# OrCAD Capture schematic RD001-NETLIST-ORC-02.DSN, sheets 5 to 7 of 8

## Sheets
5 4: size A3
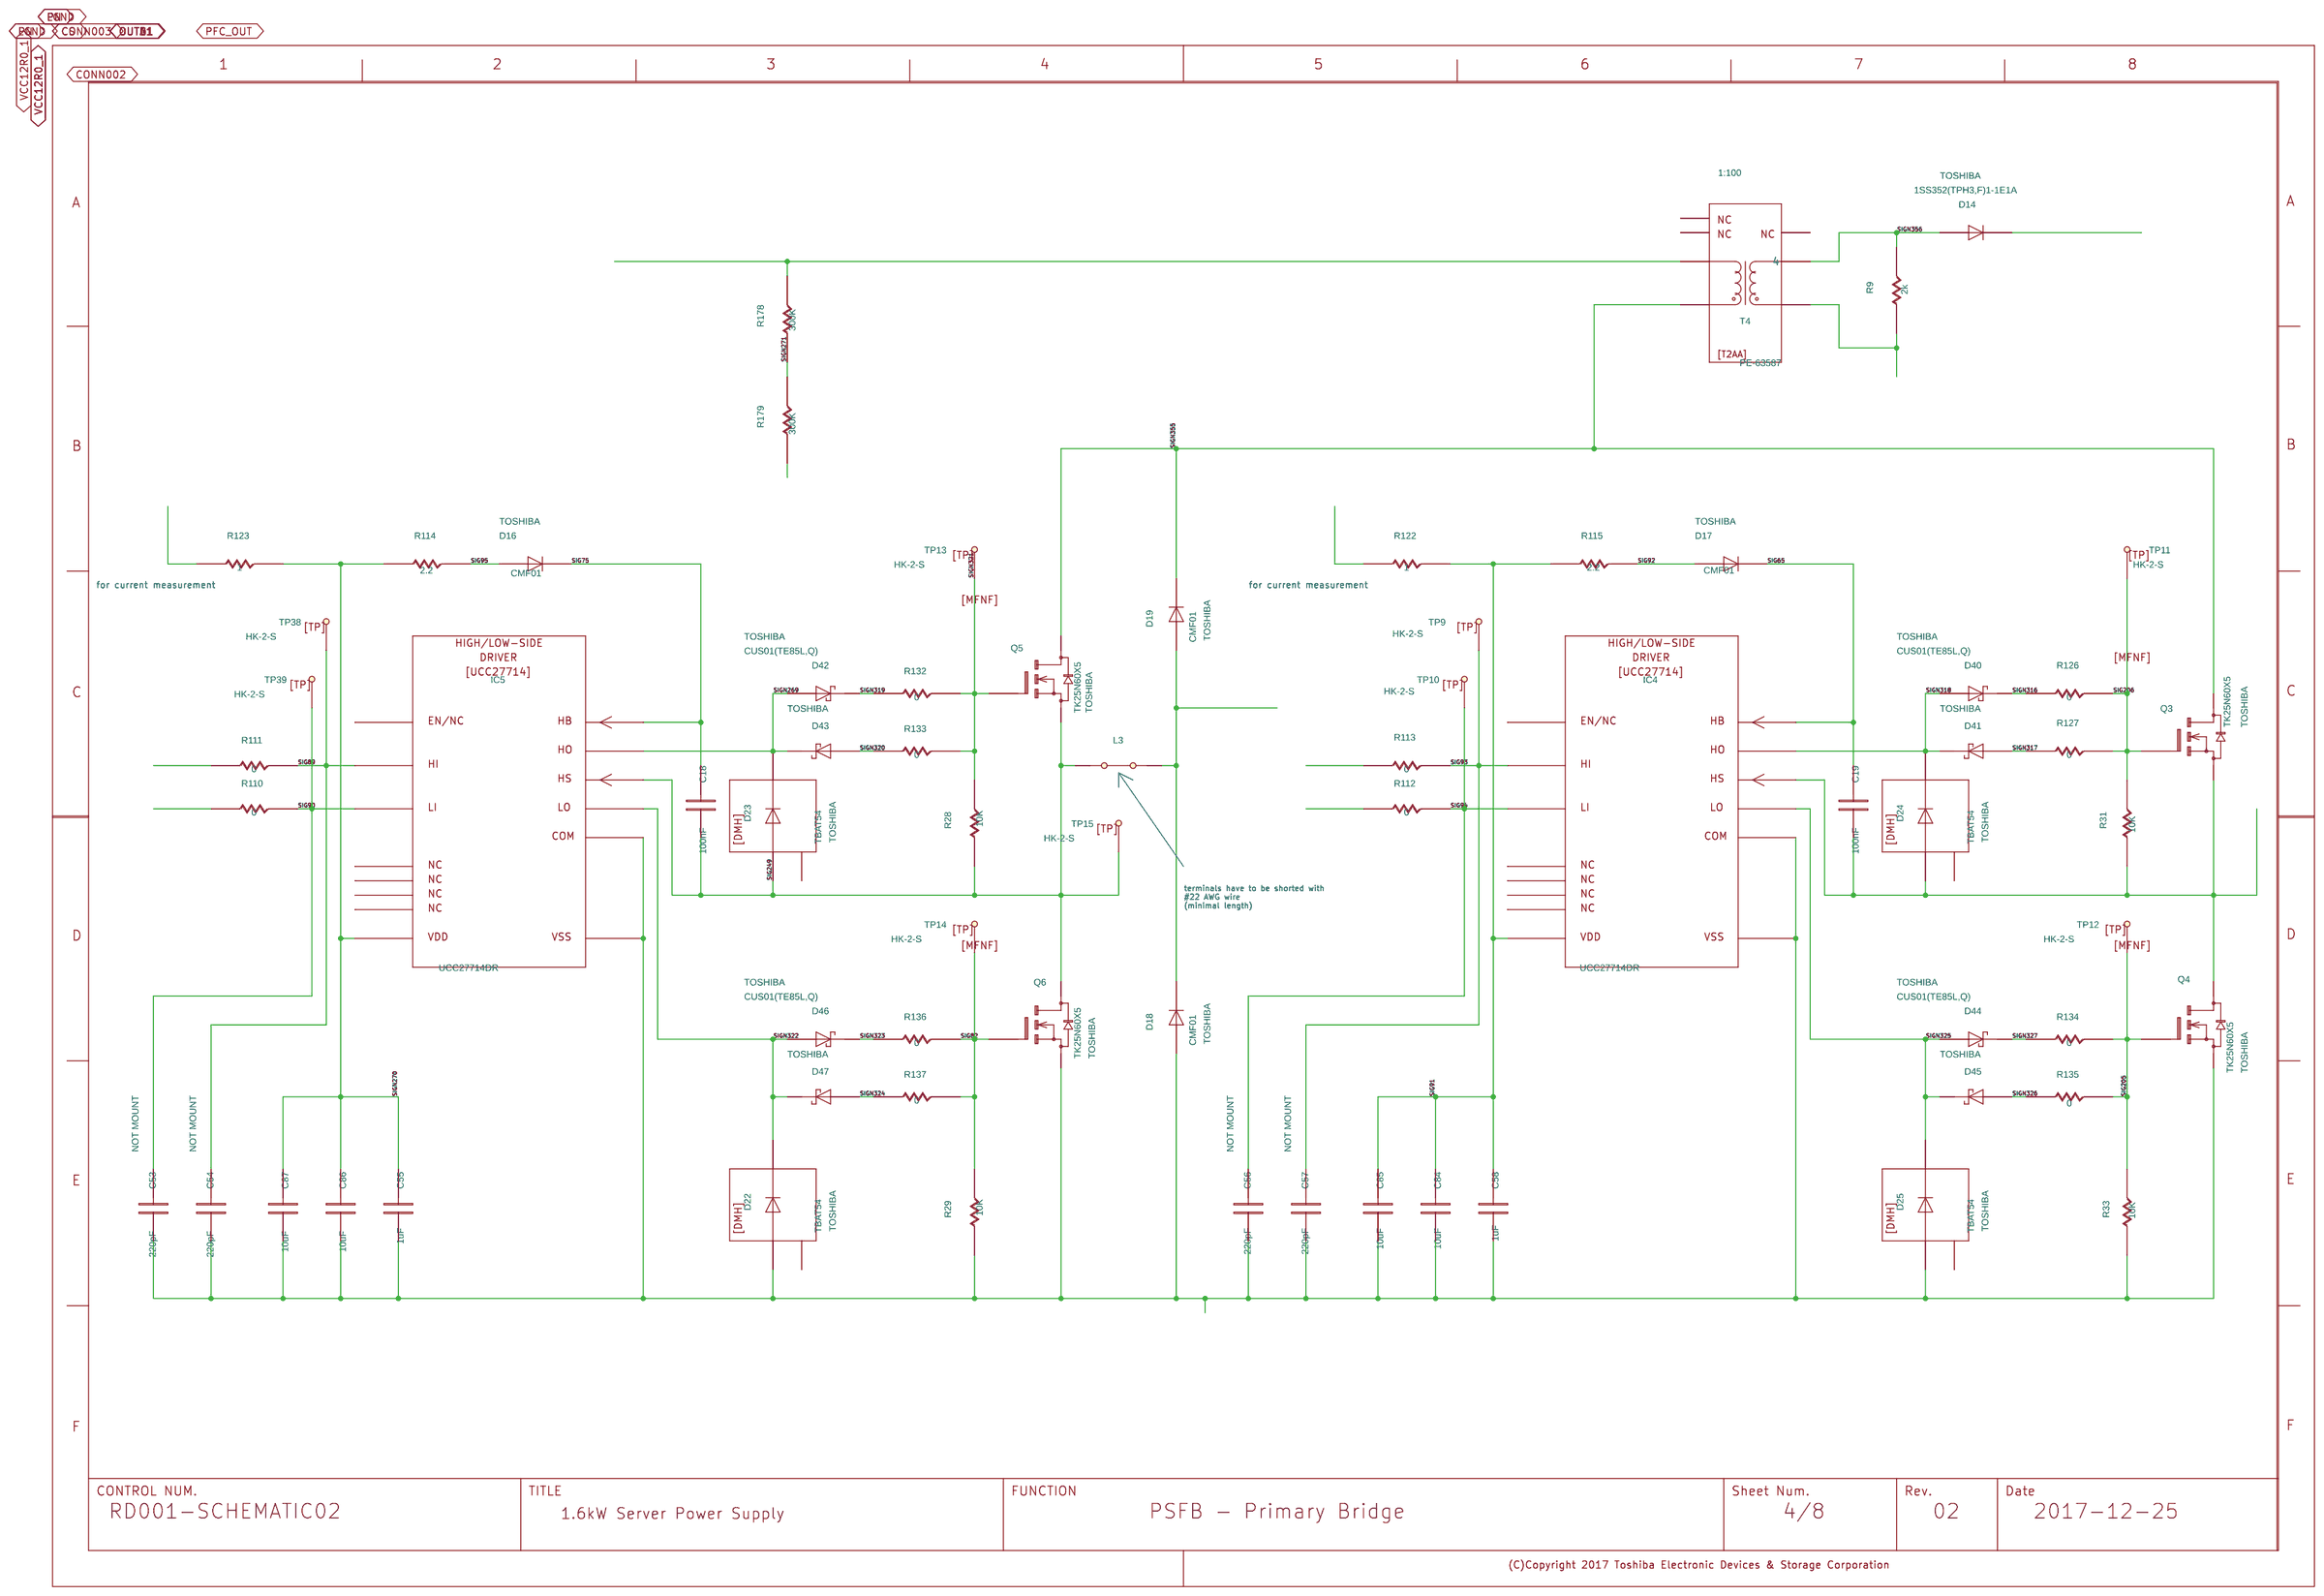
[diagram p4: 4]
6 3: size A3
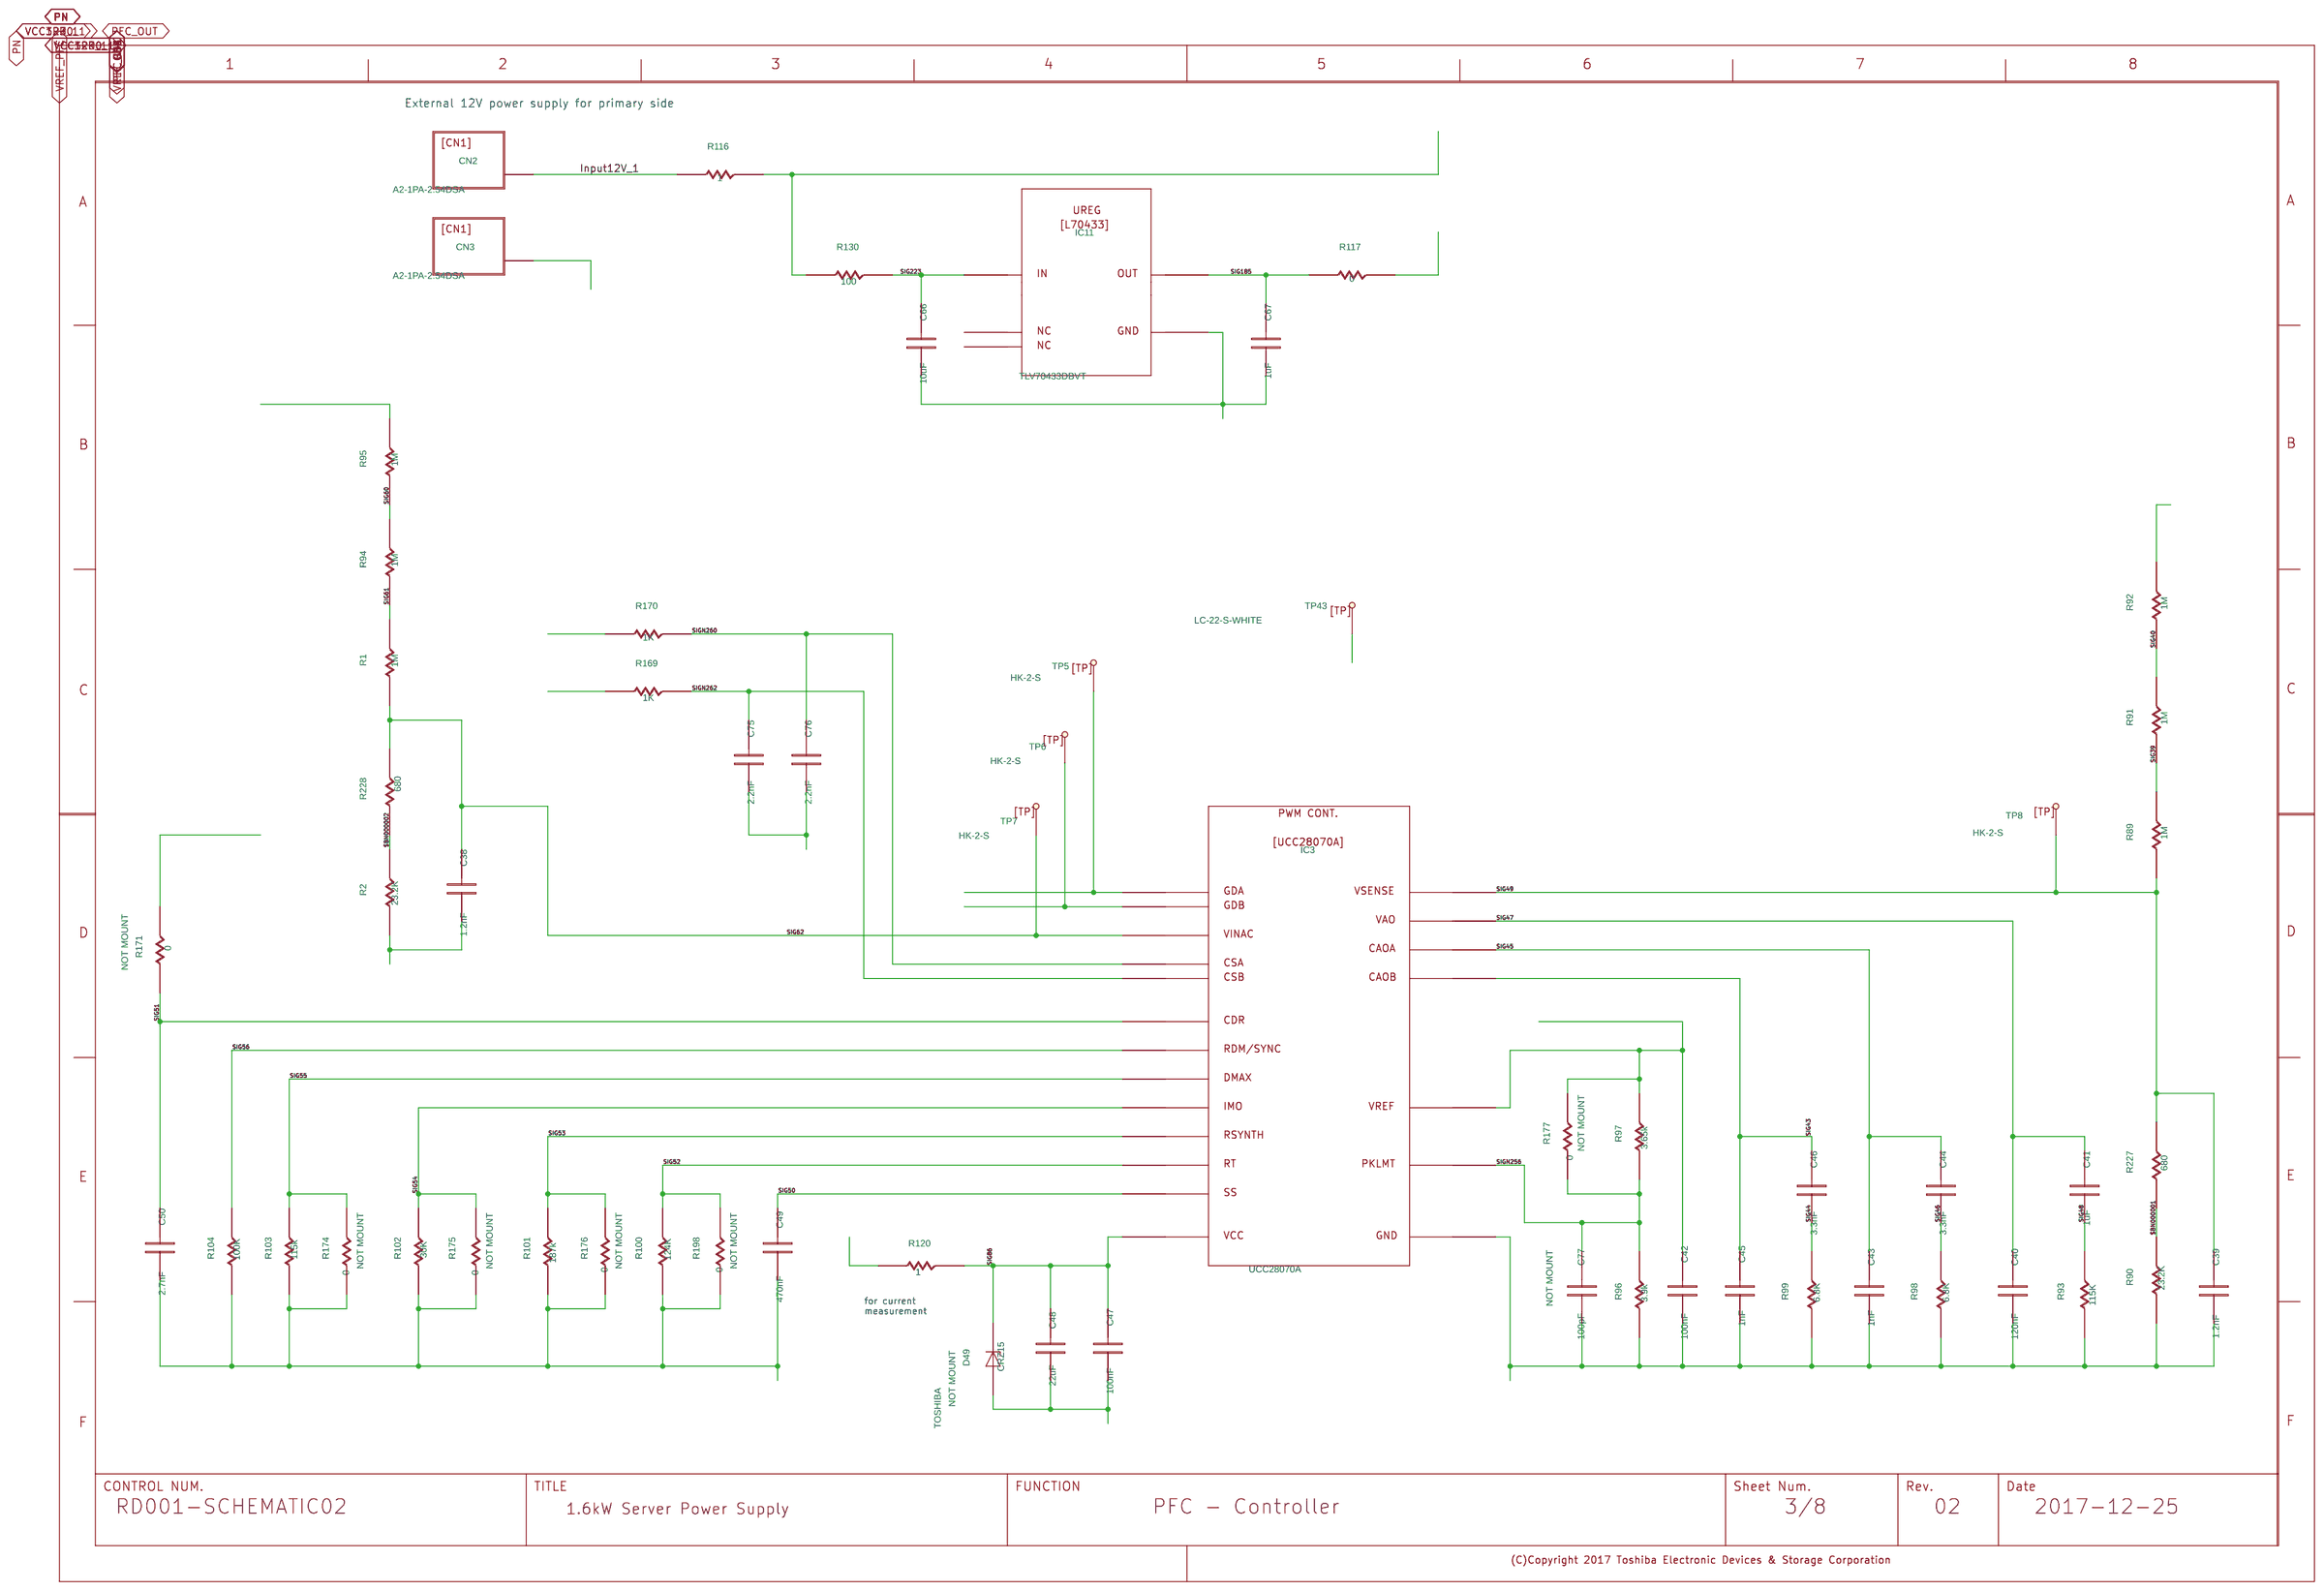
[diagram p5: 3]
7 2: size A3
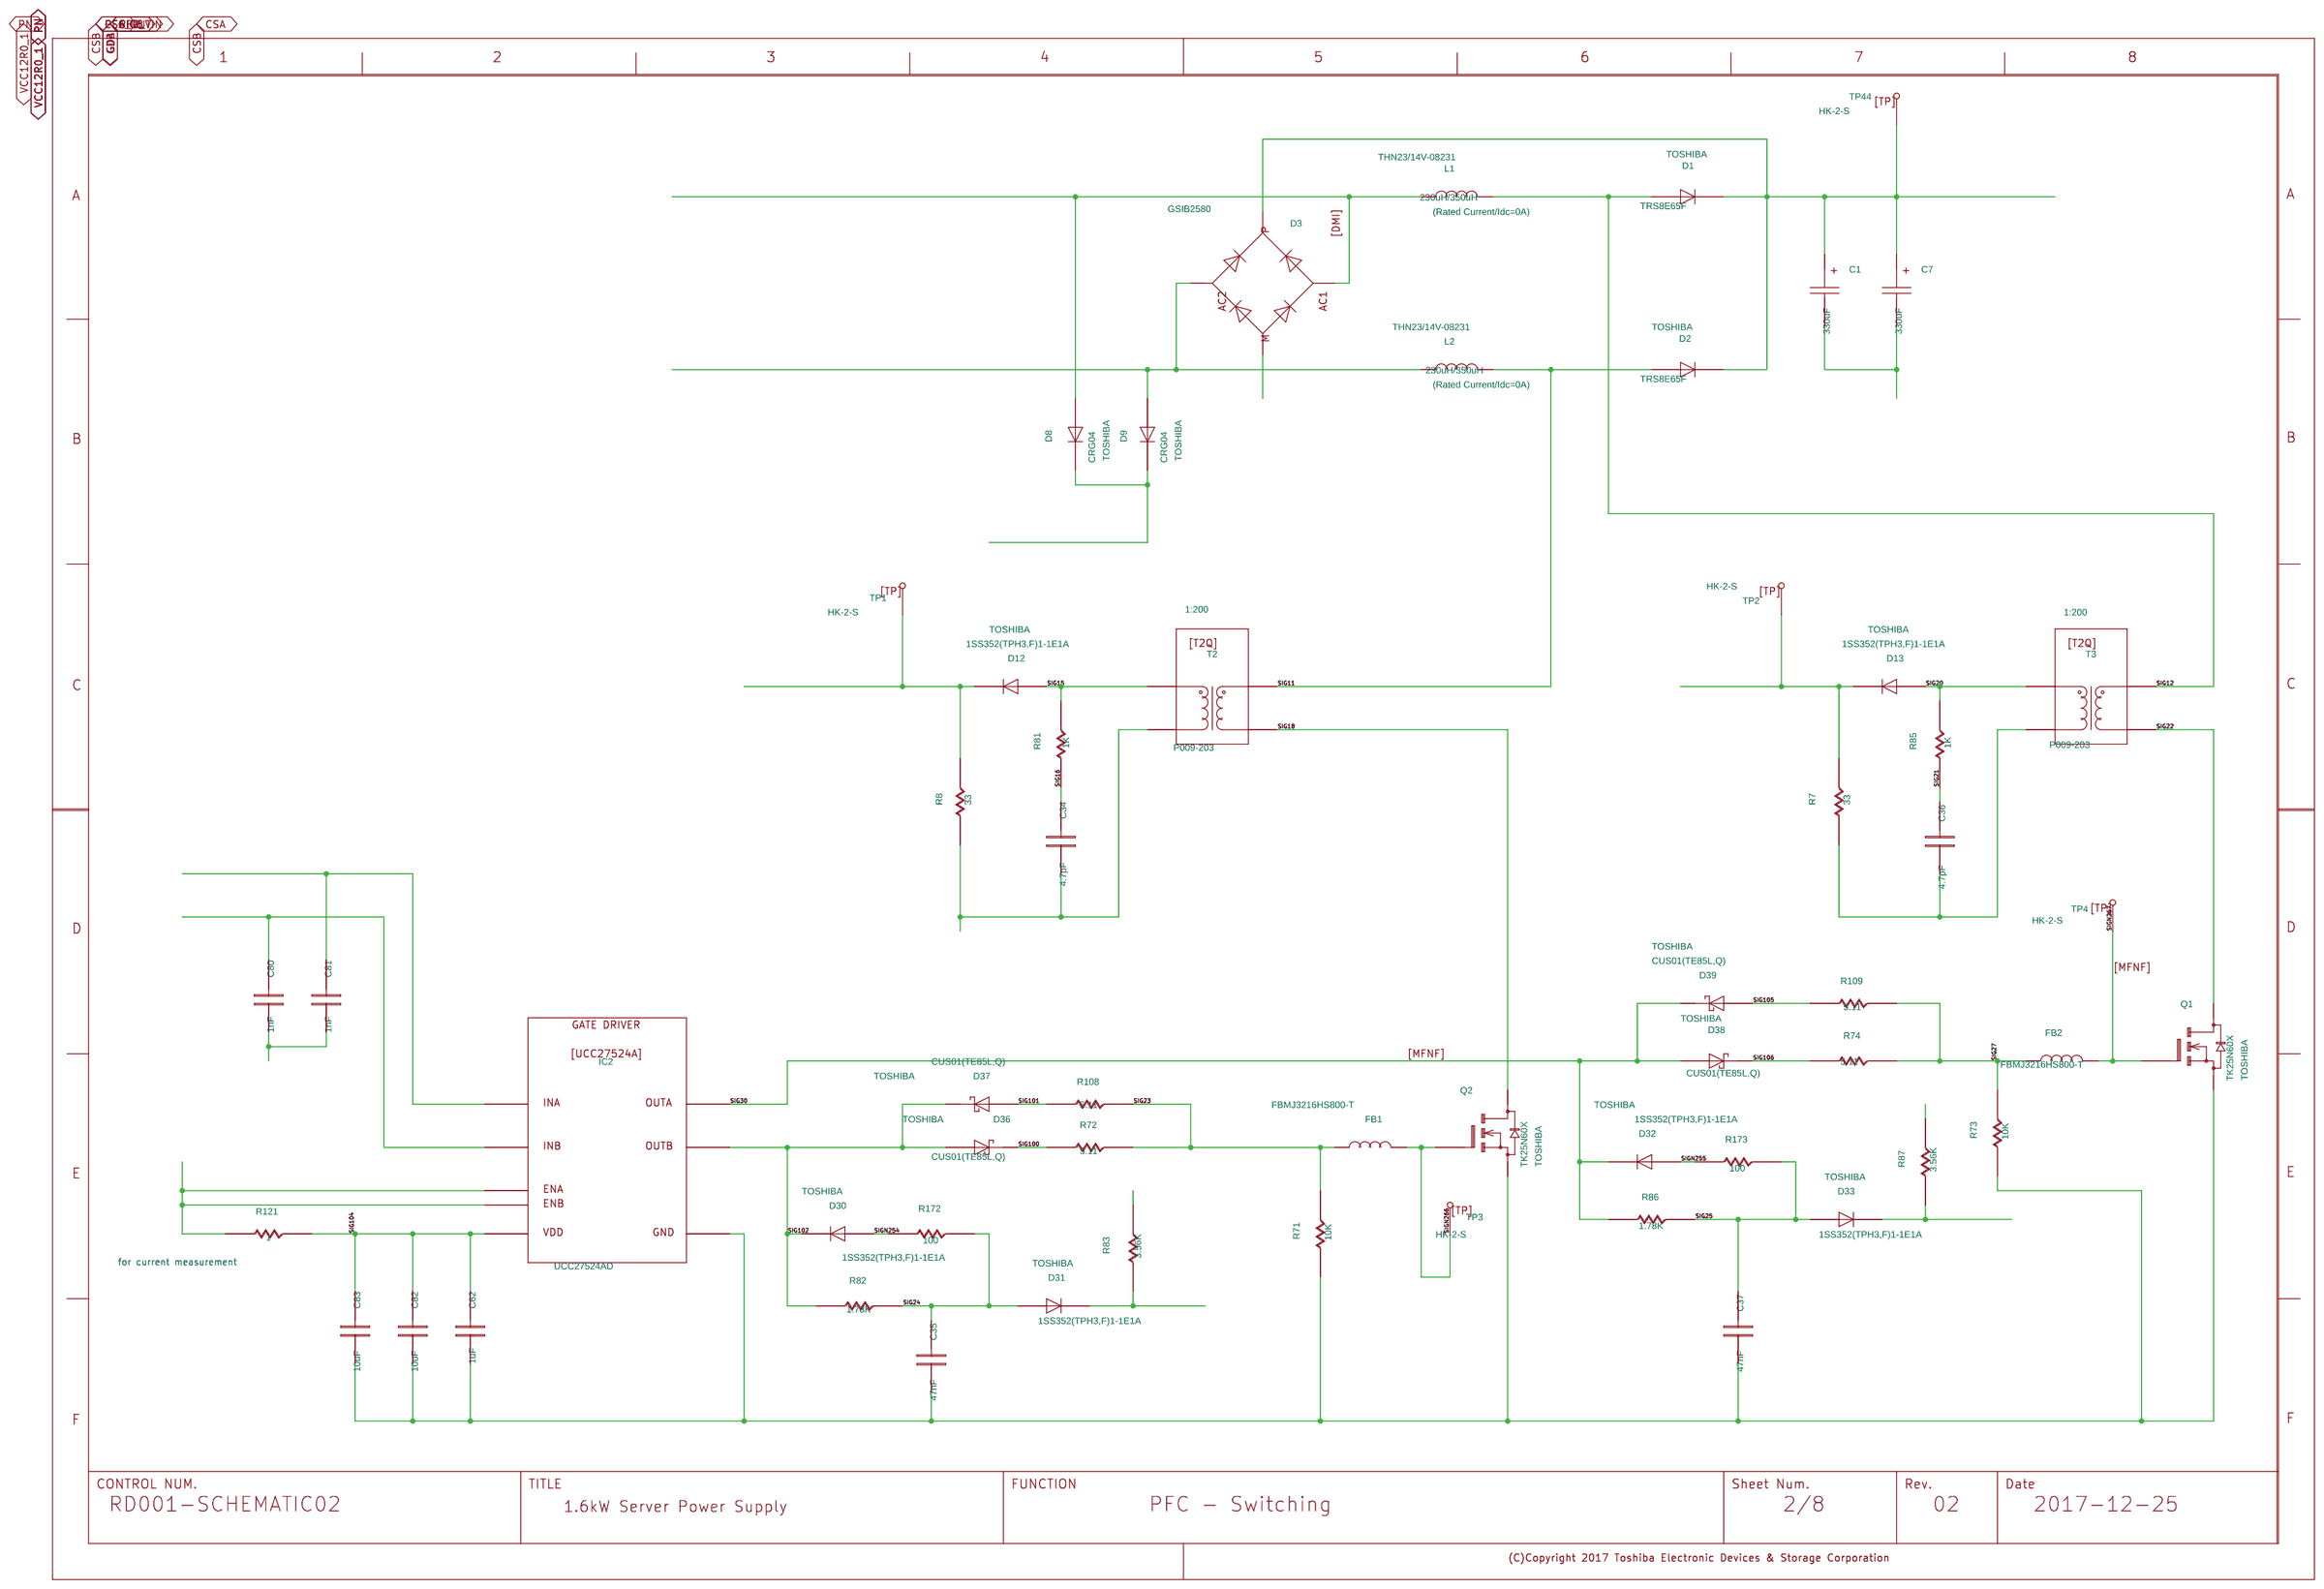
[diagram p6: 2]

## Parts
sheet 2
C1  CP
C7  CP
C34  C
C35  C
C36  C
C37  C
C62  C
C80  C
C81  C
C82  C
C83  C
D1  D
D2  D
D3  DMI
D8  D
D9  D
D12  D
D13  D
D30  D
D31  D
D32  D
D33  D
D36  SBD
D37  SBD
D38  SBD
D39  SBD
FB1  L
FB2  L
IC2  L27524
L1  L
L2  L
Q1  MFNF
Q2  MFNF
R7  R
R8  R
R71  R
R72  R
R73  R
R74  R
R81  R
R82  R
R83  R
R85  R
R86  R
R87  R
R108  R
R109  R
R121  R
R172  R
R173  R
T2  T2Q
T3  T2Q
TP1  TP
TP2  TP
TP3  TP
TP4  TP
TP44  TP
U?#6  WAKU_DEF100
sheet 3
C38  C
C39  C
C40  C
C41  C
C42  C
C43  C
C44  C
C45  C
C46  C
C47  C
C48  C
C49  C
C50  C
C66  C
C67  C
C75  C
C76  C
C77  C
CN2  CN1
CN3  CN1
D49  ZD
IC3  L28070
IC11  L70433
R1  R
R2  R
R89  R
R90  R
R91  R
R92  R
R93  R
R94  R
R95  R
R96  R
R97  R
R98  R
R99  R
R100  R
R101  R
R102  R
R103  R
R104  R
R116  R
R117  R
R120  R
R130  R
R169  R
R170  R
R171  R
R174  R
R175  R
R176  R
R177  R
R198  R
R227  R
R228  R
TP5  TP
TP6  TP
TP7  TP
TP8  TP
TP43  TP
U?#5  WAKU_DEF100
sheet 4
C18  C
C19  C
C53  C
C54  C
C55  C
C56  C
C57  C
C58  C
C84  C
C85  C
C86  C
C87  C
D14  D
D16  D
D17  D
D18  D
D19  D
D22  DMH
D23  DMH
D24  DMH
D25  DMH
D40  SBD
D41  SBD
D42  SBD
D43  SBD
D44  SBD
D45  SBD
D46  SBD
D47  SBD
IC4  L27714
IC5  L27714
L3  JP
Q3  MFNF
Q4  MFNF
Q5  MFNF
Q6  MFNF
R9  R
R28  R
R29  R
R31  R
R33  R
R110  R
R111  R
R112  R
R113  R
R114  R
R115  R
R122  R
R123  R
R126  R
R127  R
R132  R
R133  R
R134  R
R135  R
R136  R
R137  R
R178  R
R179  R
T4  T2AA
TP9  TP
TP10  TP
TP11  TP
TP12  TP
TP13  TP
TP14  TP
TP15  TP
TP38  TP
TP39  TP
U?#4  WAKU_DEF100

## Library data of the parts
C1 = CP: CAPACITANCETOLE: M; CDMASTERCADCELG: DC213N; CHIPSIZE: D35xL30; COMP: PRT_4; COMPONENTTYPE: 4; FNLEADFREETHET1GT2GMCTH1: 9_N_N; GCOUNT: 1; MAKER: RUBYCON; MAXGCOUNT: 1; NOMINALCAPACITA: 330u; OUMECLASSIFICATION: ƒAƒ‹ƒ~“d‰ðƒRƒ“ƒfƒ“ƒT; OUMEMAKER: SIT ƒ‹ƒrƒRƒ“; OUMEMAKERKATAMEI: 450MXC330M35X40; OUMEPARTTYPE: C; QUADMODEL: CON_330U; RATEDVOLTAGE: 450; SIZECODESMD: DIP; VAL1: 330uF; VAL2: 450V; VAL3: 450MXH330
C7 = CP: CAPACITANCETOLE: M; CDMASTERCADCELG: DC213N; CHIPSIZE: D35xL30; COMP: PRT_4; COMPONENTTYPE: 4; FNLEADFREETHET1GT2GMCTH1: 9_N_N; GCOUNT: 1; MAKER: RUBYCON; MAXGCOUNT: 1; NOMINALCAPACITA: 330u; OUMECLASSIFICATION: ƒAƒ‹ƒ~“d‰ðƒRƒ“ƒfƒ“ƒT; OUMEMAKER: SIT ƒ‹ƒrƒRƒ“; OUMEMAKERKATAMEI: 450MXC330M35X40; OUMEPARTTYPE: C; QUADMODEL: CON_330U; RATEDVOLTAGE: 450; SIZECODESMD: DIP; VAL1: 330uF; VAL2: 450V,}20%; VAL3: 450MXH330
C34 C36 = C: ADSMODELNAME: s_GRM1552C1H4R7CA01D; CDMASTERCADCELG: KC0005; CHIPSIZE: 1005; COMP: PRT_52; COMPONENTTYPE: 4; FNLEADFREETHET1GT2GMCTH1: N_N_N; GCOUNT: 1; MAKER: MURATA; MAXGCOUNT: 1; NOMINALCAPACITA: 4.7p; OUMECLASSIFICATION: ƒZƒ‰ƒ~ƒbƒNƒRƒ“ƒfƒ“ƒT; OUMEMAKER: MRT ºc»ì; OUMEMAKERKATAMEI: GRM1552C1H4R7CA01D; PMPRODUCTSTYPEG: DME; QUADMODEL: CON_4.7P; RATEDVOLTAGE: 50; SIZECODESMD: 1005; TEMPCHARACTERI2: CH; VAL1: 4.7pF; VAL2: 50V,}0.1pF; VAL3: GRM1555C1H4R7BA01D
C35 = C: ADSCNVFLAG: ON; ADSCOMPONENTNAME: C_1005; ADSMODELNAME: s_GCM155R11C473KA01J; CAPACITANCETOLE: K; CDMASTERCADCELG: KC0005; CHIPSIZE: 1005; COMP: PRT_52; COMPONENTTYPE: 4; FNLEADFREETHET1GT2GMCTH1: N_N_N; GCOUNT: 1; ICX_PART_MODEL: CON_47N; MAKER: MURATA; MAXGCOUNT: 1; NOMINALCAPACITA: 47n; OUMECLASSIFICATION: ƒZƒ‰ƒ~ƒbƒNƒRƒ“ƒfƒ“ƒT; OUMEMAKER: MRT ºc»ì; OUMEMAKERKATAMEI: GCM155R11C473KA01J; QUADMODEL: CON_47N; RATEDVOLTAGE: 16; SIZECODESMD: 1005; SQ_PART_MODEL: CON_47N; TEMPCHARACTERI2: R; VAL1: 47nF; VAL2: 25V,}10%; VAL3: GRM155R71E473KA88D
C37 = C: ADSMODELNAME: s_GCM155R11C473KA01J; CAPACITANCETOLE: K; CDMASTERCADCELG: KC0005; CHIPSIZE: 1005; COMP: PRT_52; COMPONENTTYPE: 4; FNLEADFREETHET1GT2GMCTH1: N_N_N; GCOUNT: 1; MAKER: MURATA; MAXGCOUNT: 1; NOMINALCAPACITA: 47n; OUMECLASSIFICATION: ƒZƒ‰ƒ~ƒbƒNƒRƒ“ƒfƒ“ƒT; OUMEMAKER: MRT ºc»ì; OUMEMAKERKATAMEI: GCM155R11C473KA01J; QUADMODEL: CON_47N; RATEDVOLTAGE: 16; SIZECODESMD: 1005; TEMPCHARACTERI2: R; VAL1: 47nF; VAL2: 25V,}10%; VAL3: GRM155R71E473KA88D
C62 = C: ADSMODELNAME: s_C1005X5R1C105M050BC; CAPACITANCETOLE: M; CDMASTERCADCELG: KC0005; CHIPSIZE: 1005; COMP: PRT_52; COMPONENTTYPE: 4; FNLEADFREETHET1GT2GMCTH1: N_N_N; GCOUNT: 1; MAKER: TDK; MAXGCOUNT: 1; NOMINALCAPACITA: 1u; OUMECLASSIFICATION: ƒZƒ‰ƒ~ƒbƒNƒRƒ“ƒfƒ“ƒT; OUMEMAKER: TDK ‚s‚c‚j; OUMEMAKERKATAMEI: C1005X5R1C105M050BC; QUADMODEL: CON_1U; RATEDVOLTAGE: 16; SIZECODESMD: 1005; VAL1: 1uF; VAL2: 25V,}20%; VAL3: C1005X5R1E105M050BC
C43 C45 C80 C81 = C: ADSMODELNAME: s_UMK105BJ102KV_F; CAPACITANCETOLE: K; CDMASTERCADCELG: KC0005; CHIPSIZE: 1005; COMP: PRT_52; COMPONENTTYPE: 4; FNLEADFREETHET1GT2GMCTH1: 2_0_N; GCOUNT: 1; MAKER: TDK; MAXGCOUNT: 1; NOMINALCAPACITA: 1n; OUMECLASSIFICATION: ƒZƒ‰ƒ~ƒbƒNƒRƒ“ƒfƒ“ƒT; OUMEMAKER: TYD ‘¾—z—U“d; OUMEMAKERKATAMEI: UMK105BJ102KV-F; PMPRODUCTSTYPEG: HD1-PC1; QUADMODEL: CON_1N; RATEDVOLTAGE: 50; SIZECODESMD: 1005; TEMPCHARACTERI2: B; VAL1: 1nF; VAL2: 50V,}10%; VAL3: UMK105BJ102KV-F
C82-C87 = C: ADSMODELNAME: s_TMK316LD106KL_T; CAPACITANCETOLE: K; CDMASTERCADCELG: KC0014; CHIPSIZE: 3216; COMP: PRT_46; COMPONENTTYPE: 4; FNLEADFREETHET1GT2GMCTH1: N_N_N; GCOUNT: 1; MAKER: TAIYO YUDEN; MAXGCOUNT: 1; NOMINALCAPACITA: 10u; OUMECLASSIFICATION: ƒZƒ‰ƒ~ƒbƒNƒRƒ“ƒfƒ“ƒT; OUMEMAKER: TYD ‘¾—z—U“d; OUMEMAKERKATAMEI: TMK316LD106KL-T; QUADMODEL: CON_10U; RATEDVOLTAGE: 25; SIZECODESMD: 3216; VAL1: 10uF; VAL2: 25V,}10%; VAL3: TMK316BJ106KL-T
D1 D2 = D: ADSMODELNAME: s_1N4148; CDMASTERCADCELG: DCR071; COMP: PRT_12; COMPONENTTYPE: 4; FNLEADFREETHET1GT2GMCTH1: N_N_N; FORWARDVOLTAGEM: 0; GCOUNT: 1; MAKER: TOSHIBA; MAXAVERAGEFORWA: 0; MAXGCOUNT: 1; MAXREPETITIVEPE: 0; MAXREVERSEVOLTA: 100; MOUNTINGFORMSMD: DIP; OUMECLASSIFICATION: ¬M_CI[h; OUMEMAKER: ROH [; OUMEMAKERKATAMEI: 1N4148; PEAKFORWARDVOLT: 0; REVERSECURRENT: 0; USERCOMPTEXT3: TOSHIBA; VAL3: TRS8E65F; ZENERVOLTAGEMAX: 0; ZENERVOLTAGEMIN: 0
D3 = DMI: ADSMODELNAME: s_D1UBA80_EMBEDED; CDMASTERCADCELG: MMK0161; COMP: PRT_53; COMPONENTTYPE: 4; FNLEADFREETHET1GT2GMCTH1: N_N_N; FORWARDVOLTAGEM: 0; GCOUNT: 1; MAKER: VISHAY; MAXAVERAGEFORWA: 800m; MAXGCOUNT: 1; MAXREPETITIVEPE: 800; MAXREVERSEVOLTA: 0; MOUNTINGFORMSMD: SMD; OUMECLASSIFICATION: êÊ®¬fq; OUMEMAKER: SDG Vd³HÆ; OUMEMAKERKATAMEI: D1UBA80_EMBEDED; OUMEPARTTYPE: D; PEAKFORWARDVOLT: 950m; REVERSECURRENT: 10u; VAL3: GSIB2580; ZENERVOLTAGEMAX: 0; ZENERVOLTAGEMIN: 0
D8 D9 = D: ADSMODELNAME: s_CRG03_T5L_TEMQ_; CDMASTERCADCELG: MMK0167; COMP: PRT_24; COMPONENTTYPE: 4; FNLEADFREETHET1GT2GMCTH1: N_N_N; FORWARDVOLTAGEM: 0; GCOUNT: 1; MAKER: TOSHIBA; MAXAVERAGEFORWA: 1; MAXGCOUNT: 1; MAXREPETITIVEPE: 400; MAXREVERSEVOLTA: 0; MOUNTINGFORMSMD: SMD; OUMECLASSIFICATION: êÊ®¬fq; OUMEMAKER: TSB “ŒŽÅ; OUMEMAKERKATAMEI: CRG03(T5L,TEMQ); PEAKFORWARDVOLT: 1.1; PMPRODUCTSTYPEG: HD1; REVERSECURRENT: 10u; USERCOMPTEXT3: TOSHIBA; VAL3: CRG04; ZENERVOLTAGEMAX: 0; ZENERVOLTAGEMIN: 0
D12-D14 D30 D32 D33 = D: ADSMODELNAME: s_1SS352_TPH3_F_1_1E1A; CDMASTERCADCELG: D81022; COMP: PRT_27; COMPONENTTYPE: 4; FNLEADFREETHET1GT2GMCTH1: N_N_N; FORWARDVOLTAGEM: 0; GCOUNT: 1; MAKER: TOSHIBA; MAXAVERAGEFORWA: 0; MAXGCOUNT: 1; MAXREPETITIVEPE: 0; MAXREVERSEVOLTA: 80; MOUNTINGFORMSMD: SMD; OUMECLASSIFICATION: ¬M_CI[h; OUMEMAKER: TSB “ŒŽÅ; OUMEMAKERKATAMEI: 1SS352(TPH3,F)1-1E1A; PEAKFORWARDVOLT: 0; REVERSECURRENT: 0; USERCOMPTEXT3: TOSHIBA; VAL1: 1SS352(TPH3,F)1-1E1A; VAL3: 1SS352(TPH3,F)1-1E1A; ZENERVOLTAGEMAX: 0; ZENERVOLTAGEMIN: 0
D31 = D: ADSCNVFLAG: ON; ADSCOMPONENTNAME: D_D; ADSMODELNAME: s_1SS352_TPH3_F_1_1E1A; CDMASTERCADCELG: D81022; COMP: PRT_27; COMPONENTTYPE: 4; FNLEADFREETHET1GT2GMCTH1: N_N_N; FORWARDVOLTAGEM: 0; GCOUNT: 1; MAKER: TOSHIBA; MAXAVERAGEFORWA: 0; MAXGCOUNT: 1; MAXREPETITIVEPE: 0; MAXREVERSEVOLTA: 80; MOUNTINGFORMSMD: SMD; OUMECLASSIFICATION: ¬M_CI[h; OUMEMAKER: TSB “ŒŽÅ; OUMEMAKERKATAMEI: 1SS352(TPH3,F)1-1E1A; PEAKFORWARDVOLT: 0; REVERSECURRENT: 0; USERCOMPTEXT3: TOSHIBA; VAL1: 1SS352(TPH3,F)1-1E1A; VAL3: 1SS352(TPH3,F)1-1E1A; ZENERVOLTAGEMAX: 0; ZENERVOLTAGEMIN: 0
D36-D39 = SBD: ADSMODELNAME: s_CUS01_TE85L_Q_; CDMASTERCADCELG: MM0042; COMP: PRT_11; COMPONENTTYPE: 4; FNLEADFREETHET1GT2GMCTH1: 2_0_N; FORWARDVOLTAGEM: 0; GCOUNT: 1; MAKER: TOSHIBA; MAXAVERAGEFORWA: 1; MAXGCOUNT: 1; MAXREPETITIVEPE: 30; MAXREVERSEVOLTA: 0; MOUNTINGFORMSMD: SMD; OUMECLASSIFICATION: ¬p®¬fq/VbgLoA_CI[h; OUMEMAKER: TSB “ŒŽÅ; OUMEMAKERKATAMEI: CUS01(TE85L,Q); OUMEPARTTYPE: D; PEAKFORWARDVOLT: 370m; PMPRODUCTSTYPEG: PC1; REVERSECURRENT: 500u; USERCOMPTEXT3: TOSHIBA; VAL1: CUS01(TE85L,Q); VAL3: CUS01(TE85L,Q); ZENERVOLTAGEMAX: 0; ZENERVOLTAGEMIN: 0
FB1 FB2 = L: COMP: PRT_30; COMPONENTTYPE: 4; MAKER: TAIYO YUDEN; VAL3: FBMJ3216HS800-T
IC2 = L27524: COMP: PRT_63; COMPONENTTYPE: 4; MAKER: TEXAS; VAL3: UCC27524AD
L1 L2 = L: COMP: PRT_41; COMPONENTTYPE: 4; GCOUNT: 1; INDUCTANCEMAX: 0; INDUCTANCEMIN: 0; MAKER: TMP; MAXGCOUNT: 1; MOUNTINGFORMSMD: DIP; NOMINALINDUCTA1: 100u; NOMINALINDUCTA2: K; VAL1: 230uH/350uH; VAL2: (Rated Current/Idc=0A); VAL3: THN23/14V-08231
Q1 Q2 = MFNF: COMP: PRT_31; COMPONENTTYPE: 4; MAKER: TOSHIBA; USERCOMPTEXT3: TOSHIBA; VAL3: TK25N60X
R7 R8 = R: CHIPSIZE: 3225; COMP: PRT_23; COMPONENTTYPE: 4; MAKER: PANASONIC; VAL1: 33; VAL2: 500mW,}5%; VAL3: ERJ-14YJ330U
R28 R29 R31 R33 R71 R73 = R: ADSMODELNAME: s_RK73B1JTTD103J@@; CDMASTERCADCELG: KC0133; CHIPSIZE: 1608; COMP: PRT_8; COMPONENTTYPE: 4; FNLEADFREETHET1GT2GMCTH1: N_N_N; GCOUNT: 1; MAKER: KOA; MAXGCOUNT: 1; MOUNTINGFORMSMD: SMD; NOMINALRESISTAN: 10K; OUMECLASSIFICATION: \ÊÀpÅèïRí; OUMEMAKER: KOA R[A; OUMEMAKERKATAMEI: RK73B1JTTD103J@@; POWERRATING: 100m; QUADMODEL: RES_10K; RESISTANCETOLER: J; SIZECODESMD: 1608; VAL1: 10K; VAL2: 100mW,}5%; VAL3: RK73B1JTTD103J
R72 R74 R108 R109 = R: ADSMODELNAME: s_RK73H2BTTD6R80F; CDMASTERCADCELG: DR901A; CHIPSIZE: 3216; COMP: PRT_5; COMPONENTTYPE: 4; FNLEADFREETHET1GT2GMCTH1: 3_1_N; GCOUNT: 1; MAKER: BOURNS; MAXGCOUNT: 1; MOUNTINGFORMSMD: SMD; NOMINALRESISTAN: 6.8; OUMECLASSIFICATION: \ÊÀpÅèïRí; OUMEMAKER: KOA R[A; OUMEMAKERKATAMEI: RK73H2BTTD6R80F; POWERRATING: 125m; QUADMODEL: RES_6.8; RESISTANCETOLER: F; SIZECODESMD: 3216; VAL1: 5.11; VAL2: 500mW,}1%; VAL3: CRM1206-FX-5R11ELF
R81 R85 = R: ADSMODELNAME: s_RK73B1JRTTD102J; CDMASTERCADCELG: KCK0203; CHIPSIZE: 1608; COMP: PRT_8; COMPONENTTYPE: 4; FNLEADFREETHET1GT2GMCTH1: N_N_N; GCOUNT: 1; MAKER: KOA; MAXGCOUNT: 1; MOUNTINGFORMSMD: SMD; NOMINALRESISTAN: 1K; OUMECLASSIFICATION: \ÊÀpÅèïRí; OUMEMAKER: KOA R[A; OUMEMAKERKATAMEI: RK73B1JRTTD102J; PMPRODUCTSTYPEG: DME; POWERRATING: 100m; QUADMODEL: RES_1K; RESISTANCETOLER: J; SIZECODESMD: 1608; VAL1: 1K; VAL2: 125mW,}5%; VAL3: RK73B1JTTD102J
R82 = R: ADSMODELNAME: s_RK73H1JTD1741F; CDMASTERCADCELG: KC0008; CHIPSIZE: 1608; COMP: PRT_8; COMPONENTTYPE: 4; FNLEADFREETHET1GT2GMCTH1: N_N_N; GCOUNT: 1; MAKER: PANASONIC; MAXGCOUNT: 1; MOUNTINGFORMSMD: SMD; NOMINALRESISTAN: 1.74K; OUMECLASSIFICATION: \ÊÀpÅèïRí; OUMEMAKER: KOA R[A; OUMEMAKERKATAMEI: RK73H1JTD1741F; POWERRATING: 63m; QUADMODEL: RES_1.74K; RESISTANCETOLER: F; SIZECODESMD: 1608; VAL1: 1.78K; VAL2: 100mW,}1%; VAL3: ERJ-3EKF1781V
R83 R87 = R: ADSMODELNAME: s_ERJ3GEYF362V; CDMASTERCADCELG: DR802R; CHIPSIZE: 1608; COMP: PRT_8; COMPONENTTYPE: 4; FNLEADFREETHET1GT2GMCTH1: 3_1_N; GCOUNT: 1; MAKER: PANASONIC; MAXGCOUNT: 1; MOUNTINGFORMSMD: SMD; NOMINALRESISTAN: 3.6K; OUMECLASSIFICATION: \ÊÀpÅèïRí; OUMEMAKER: NAE pi\jbNGNgjbNfoCX; OUMEMAKERKATAMEI: ERJ3GEYF362V; POWERRATING: 63m; QUADMODEL: RES_3.6K; RESISTANCETOLER: F; SIZECODESMD: 1608; VAL1: 3.56K; VAL2: 100mW,}1%; VAL3: ERJ-3EKF3571V
R86 = R: ADSCNVFLAG: ON; ADSCOMPONENTNAME: R_1608; ADSMODELNAME: s_RK73H1JTD1741F; CDMASTERCADCELG: KC0008; CHIPSIZE: 1608; COMP: PRT_8; COMPONENTTYPE: 4; FNLEADFREETHET1GT2GMCTH1: N_N_N; GCOUNT: 1; ICX_PART_MODEL: RES_1.74K; MAKER: PANASONIC; MAXGCOUNT: 1; MOUNTINGFORMSMD: SMD; NOMINALRESISTAN: 1.74K; OUMECLASSIFICATION: \ÊÀpÅèïRí; OUMEMAKER: KOA R[A; OUMEMAKERKATAMEI: RK73H1JTD1741F; POWERRATING: 63m; QUADMODEL: RES_1.74K; RESISTANCETOLER: F; SIZECODESMD: 1608; SQ_PART_MODEL: RES_1.74K; VAL1: 1.78K; VAL2: 100mW,}1%; VAL3: ERJ-3EKF1781V
R116 R120 R121 = R: ADSMODELNAME: s_ERJ3GEYJ1R0V; CDMASTERCADCELG: KC0008; CHIPSIZE: 1608; COMP: PRT_8; COMPONENTTYPE: 4; FNLEADFREETHET1GT2GMCTH1: 2_1_N; GCOUNT: 1; MAKER: PANASONIC; MAXGCOUNT: 1; MOUNTINGFORMSMD: SMD; NOMINALRESISTAN: 1; OUMECLASSIFICATION: \ÊÀpÅèïRí; OUMEMAKER: NAE pi\jbNGNgjbNfoCX; OUMEMAKERKATAMEI: ERJ3GEYJ1R0V; PMPRODUCTSTYPEG: PC1; POWERRATING: 63m; QUADMODEL: RES_1; RESISTANCETOLER: J; SIZECODESMD: 1608; VAL1: 1; VAL2: 100mW,}5%; VAL3: ERJ-3GEYJ1R0V
R172 R173 = R: CHIPSIZE: 1608; COMP: PRT_8; COMPONENTTYPE: 4; MAKER: KOA; VAL1: 100; VAL2: 125mW,}5%; VAL3: RK73B1JTTD101J
T2 T3 = T2Q: ADSMODELNAME: s_CT332920S_46; CDMASTERCADCELG: DT0334; COMP: PRT_7; COMPONENTTYPE: 4; FNLEADFREETHET1GT2GMCTH1: N_N_N; GCOUNT: 1; INPUTVOLTAGE: 99.999K; MAINOUTPUTVOLTA: 99.999K; MAKER: PONY; MAXGCOUNT: 1; MAXRATEDCURREN1: 0; MOUNTINGFORMSMD: DIP; OUMECLASSIFICATION: “dŒ¹ƒgƒ‰ƒ“ƒX; OUMEMAKER: TDK ‚s‚c‚j; OUMEMAKERKATAMEI: CT332920S-46; OUMEPARTTYPE: T; PRIMARYINDUCTAN: 0; RATEDFREQ: 0; RATEDOUTPUT: 99.999K; RATEDOUTPUTVOLT: 0; VAL1: 1:200; VAL3: P009-203
TP1-TP15 TP38 TP39 TP44 = TP: COMP: PRT_44; COMPONENTKIND: 111; COMPONENTTYPE: 4; MAKER: MAC8; VAL3: HK-2-S
U?#6 = WAKU_DEF100: COMPONENTTYPE: 2; DATE: 2017-12-25; DESIGNED: TOSHIBA; DRAWINGNUMBER: RD001-SCHEMATIC02; FUNCTION: PFC - Switching; PAGENUMBER: 2; REVISION: 02; SAVEAREA0: -45080,-4508,463680,304612; SHEETNUMBER: 2/8; TIME: 10:19:22; TITLE: 1.6kW Server Power Supply; UPDATEDATE: 2017/12/25; UPDATETIME: 13:49:57; UPDATEUSER: f1043010
C38 C39 = C: ADSMODELNAME: s_UMK105BJ122KV_F; CAPACITANCETOLE: K; CDMASTERCADCELG: KC0005; CHIPSIZE: 1005; COMP: PRT_52; COMPONENTTYPE: 4; FNLEADFREETHET1GT2GMCTH1: 2_0_N; GCOUNT: 1; MAKER: TDK; MAXGCOUNT: 1; NOMINALCAPACITA: 1.2n; OUMECLASSIFICATION: ƒZƒ‰ƒ~ƒbƒNƒRƒ“ƒfƒ“ƒT; OUMEMAKER: TYD ‘¾—z—U“d; OUMEMAKERKATAMEI: UMK105BJ122KV-F; PMPRODUCTSTYPEG: HD1; QUADMODEL: CON_1.2N; RATEDVOLTAGE: 50; SIZECODESMD: 1005; TEMPCHARACTERI2: B; VAL1: 1.2nF; VAL2: 50V,}10%; VAL3: UMK105BJ122KV-F
C40 = C: ADSMODELNAME: s_GCM188R71E154KA37D; CAPACITANCETOLE: K; CDMASTERCADCELG: KC0008; CHIPSIZE: 1608; COMP: PRT_48; COMPONENTTYPE: 4; FNLEADFREETHET1GT2GMCTH1: N_N_N; GCOUNT: 1; MAKER: MURATA; MAXGCOUNT: 1; NOMINALCAPACITA: 150n; OUMECLASSIFICATION: ƒZƒ‰ƒ~ƒbƒNƒRƒ“ƒfƒ“ƒT; OUMEMAKER: MRT ºc»ì; OUMEMAKERKATAMEI: GCM188R71E154KA37D; PMPRODUCTSTYPEG: DME; QUADMODEL: CON_150N; RATEDVOLTAGE: 25; SIZECODESMD: 1608; VAL1: 120nF; VAL2: 25V,}10%; VAL3: GRM188R71E124KA01D
C41 = C: ADSMODELNAME: s_GCM31CR71H155KA55L; CAPACITANCETOLE: K; CHIPSIZE: 2012; COMP: PRT_32; COMPONENTTYPE: 4; GCOUNT: 1; MAKER: TDK; MAXGCOUNT: 1; NOMINALCAPACITA: 1.5u; PMPRODUCTSTYPEG: DME; RATEDVOLTAGE: 50; VAL1: 1uF; VAL2: 25V,}10%; VAL3: C2012X7R1E105K125AB
C42 = C: ADSMODELNAME: s_GRM155R71E104KE14D; CAPACITANCETOLE: K; CDMASTERCADCELG: KC0005; CHIPSIZE: 1005; COMP: PRT_52; COMPONENTTYPE: 4; FNLEADFREETHET1GT2GMCTH1: N_N_N; GCOUNT: 1; MAKER: TDK; MAXGCOUNT: 1; NOMINALCAPACITA: 100n; OUMECLASSIFICATION: ƒZƒ‰ƒ~ƒbƒNƒRƒ“ƒfƒ“ƒT; OUMEMAKER: MRT ºc»ì; OUMEMAKERKATAMEI: GRM155R71E104KE14D; QUADMODEL: CON_100N; RATEDVOLTAGE: 25; SIZECODESMD: 1005; VAL1: 100nF; VAL2: 25V,}10%; VAL3: C1005X7R1E104K050BB
C44 C46 = C: ADSMODELNAME: s_C1005JB1E332KT; CAPACITANCETOLE: K; CDMASTERCADCELG: KC0005; CHIPSIZE: 1005; COMP: PRT_52; COMPONENTTYPE: 4; FNLEADFREETHET1GT2GMCTH1: N_N_N; GCOUNT: 1; MAKER: TDK; MAXGCOUNT: 1; NOMINALCAPACITA: 3.3n; OUMECLASSIFICATION: ƒZƒ‰ƒ~ƒbƒNƒRƒ“ƒfƒ“ƒT; OUMEMAKER: TDK ‚s‚c‚j; OUMEMAKERKATAMEI: C1005JB1E332KT; QUADMODEL: CON_3.3N; RATEDVOLTAGE: 25; SIZECODESMD: 1005; VAL1: 3.3nF; VAL2: 25V,}10%; VAL3: CGJ2B2X7R1E332K050BA
C47 = C: ADSCNVFLAG: ON; ADSCOMPONENTNAME: C_1005; ADSMODELNAME: s_GRM155R71E104KE14D; CAPACITANCETOLE: K; CDMASTERCADCELG: KC0005; CHIPSIZE: 1005; COMP: PRT_52; COMPONENTTYPE: 4; FNLEADFREETHET1GT2GMCTH1: N_N_N; GCOUNT: 1; ICX_PART_MODEL: CON_100N; MAKER: TDK; MAXGCOUNT: 1; NOMINALCAPACITA: 100n; OUMECLASSIFICATION: ƒZƒ‰ƒ~ƒbƒNƒRƒ“ƒfƒ“ƒT; OUMEMAKER: MRT ºc»ì; OUMEMAKERKATAMEI: GRM155R71E104KE14D; QUADMODEL: CON_100N; RATEDVOLTAGE: 25; SIZECODESMD: 1005; SQ_PART_MODEL: CON_100N; VAL1: 100nF; VAL2: 25V,}10%; VAL3: C1005X7R1E104K050BB
C48 = C: ADSMODELNAME: s_GRM31CB31E226ME15D; CAPACITANCETOLE: M; CDMASTERCADCELG: KC0014; CHIPSIZE: 3216; COMP: PRT_51; COMPONENTTYPE: 4; FNLEADFREETHET1GT2GMCTH1: N_N_N; GCOUNT: 1; MAKER: MURATA; MAXGCOUNT: 1; NOMINALCAPACITA: 22u; OUMECLASSIFICATION: ƒZƒ‰ƒ~ƒbƒNƒRƒ“ƒfƒ“ƒT; OUMEMAKER: MRT ºc»ì; OUMEMAKERKATAMEI: GRM31CB31E226ME15D; QUADMODEL: CON_22U; RATEDVOLTAGE: 25; SIZECODESMD: 3216; TEMPCHARACTERI2: B; VAL1: 22uF; VAL2: 25V,}10%; VAL3: GRM31CR61E226KE15L
C49 = C: ADSMODELNAME: s_GRM155R71E104KE14D; CAPACITANCETOLE: K; CDMASTERCADCELG: KC0005; CHIPSIZE: 1005; COMP: PRT_52; COMPONENTTYPE: 4; FNLEADFREETHET1GT2GMCTH1: N_N_N; GCOUNT: 1; MAKER: TDK; MAXGCOUNT: 1; NOMINALCAPACITA: 100n; OUMECLASSIFICATION: ƒZƒ‰ƒ~ƒbƒNƒRƒ“ƒfƒ“ƒT; OUMEMAKER: MRT ºc»ì; OUMEMAKERKATAMEI: GRM155R71E104KE14D; QUADMODEL: CON_100N; RATEDVOLTAGE: 25; SIZECODESMD: 1005; VAL1: 470nF; VAL2: 25V,}10%; VAL3: C1005X5R1E474K050BB
C50 = C: ADSMODELNAME: s_UMK105BJ272KV_F; CAPACITANCETOLE: K; CDMASTERCADCELG: DC834K; CHIPSIZE: 1005; COMP: PRT_52; COMPONENTTYPE: 4; FNLEADFREETHET1GT2GMCTH1: 3_0_N; GCOUNT: 1; MAKER: TDK; MAXGCOUNT: 1; NOMINALCAPACITA: 2.7n; OUMECLASSIFICATION: ƒZƒ‰ƒ~ƒbƒNƒRƒ“ƒfƒ“ƒT; OUMEMAKER: TYD ‘¾—z—U“d; OUMEMAKERKATAMEI: UMK105BJ272KV-F; PMPRODUCTSTYPEG: PC1; QUADMODEL: CON_2.7N; RATEDVOLTAGE: 50; SIZECODESMD: 1005; TEMPCHARACTERI2: B; VAL1: 2.7nF; VAL2: 50V,}10%; VAL3: UMK105BJ272KV-F
C66 = C: ADSMODELNAME: s_ZRB18AR61E106ME01L; CAPACITANCETOLE: M; CDMASTERCADCELG: KC0167; CHIPSIZE: 1608; COMP: PRT_48; COMPONENTTYPE: 4; FNLEADFREETHET1GT2GMCTH1: N_N_N; GCOUNT: 1; MAKER: TDK; MAXGCOUNT: 1; NOMINALCAPACITA: 10u; OUMECLASSIFICATION: ƒZƒ‰ƒ~ƒbƒNƒRƒ“ƒfƒ“ƒT; OUMEMAKER: MRT ºc»ì; OUMEMAKERKATAMEI: ZRB18AR61E106ME01L; QUADMODEL: CON_10U; RATEDVOLTAGE: 25; SIZECODESMD: 1608; VAL1: 10uF; VAL2: 25V,}20%; VAL3: C1608X5R1E106M080AC
C67 = C: ADSCNVFLAG: ON; ADSCOMPONENTNAME: C_1608; ADSMODELNAME: s_GRM185B31E105KA12D; CAPACITANCETOLE: K; CDMASTERCADCELG: KC0008; CHIPSIZE: 1005; COMP: PRT_52; COMPONENTTYPE: 4; FNLEADFREETHET1GT2GMCTH1: N_N_N; GCOUNT: 1; ICX_PART_MODEL: CON_1U; MAKER: TDK; MAXGCOUNT: 1; NOMINALCAPACITA: 1u; OUMECLASSIFICATION: ƒZƒ‰ƒ~ƒbƒNƒRƒ“ƒfƒ“ƒT; OUMEMAKER: MRT ºc»ì; OUMEMAKERKATAMEI: GRM185B31E105KA12D; PMPRODUCTSTYPEG: HD1; QUADMODEL: CON_1U; RATEDVOLTAGE: 25; SIZECODESMD: 1608; SQ_PART_MODEL: CON_1U; TEMPCHARACTERI2: B; VAL1: 1uF; VAL2: 25V,}20%; VAL3: C1005X5R1E105M050BC
C75 = C: ADSMODELNAME: s_UMK105BJ222KV_F; CAPACITANCETOLE: K; CDMASTERCADCELG: KC0005; CHIPSIZE: 1005; COMP: PRT_52; COMPONENTTYPE: 4; FNLEADFREETHET1GT2GMCTH1: 2_0_N; GCOUNT: 1; MAKER: TDK; MAXGCOUNT: 1; NOMINALCAPACITA: 2.2n; OUMECLASSIFICATION: ƒZƒ‰ƒ~ƒbƒNƒRƒ“ƒfƒ“ƒT; OUMEMAKER: TYD ‘¾—z—U“d; OUMEMAKERKATAMEI: UMK105BJ222KV-F; PMPRODUCTSTYPEG: HD1-PC1; QUADMODEL: CON_2.2N; RATEDVOLTAGE: 50; SIZECODESMD: 1005; TEMPCHARACTERI2: B; VAL1: 2.2nF; VAL2: 50V,}10%; VAL3: UMK105BJ222KV-F
C76 = C: ADSMODELNAME: s_UMK105BJ222KV_F; CAPACITANCETOLE: K; CDMASTERCADCELG: KC0005; CHIPSIZE: 1005; COMP: PRT_52; COMPONENTTYPE: 4; FNLEADFREETHET1GT2GMCTH1: 2_0_N; GCOUNT: 1; MAKER: TDK; MAXGCOUNT: 1; NOMINALCAPACITA: 2.2n; OLDCOMPONENTID: 99; OUMECLASSIFICATION: ƒZƒ‰ƒ~ƒbƒNƒRƒ“ƒfƒ“ƒT; OUMEMAKER: TYD ‘¾—z—U“d; OUMEMAKERKATAMEI: UMK105BJ222KV-F; PMPRODUCTSTYPEG: HD1-PC1; QUADMODEL: CON_2.2N; RATEDVOLTAGE: 50; SIZECODESMD: 1005; TEMPCHARACTERI2: B; VAL1: 2.2nF; VAL2: 50V,}10%; VAL3: UMK105BJ222KV-F
C77 = C: CHIPSIZE: 1608; COMP: PRT_48; COMPONENTTYPE: 4; MAKER: MURATA; NOTMOUNT: NOT MOUNT; VAL1: 100pF; VAL2: 50V,}5%; VAL3: GRM1885C1H101JA01D
CN2 CN3 = CN1: AUTHOR: user1; COMP: PRT_57; COMPONENTKIND: 135; COMPONENTTYPE: 4; DATE: 2004/01/19; MAKER: HIROSE; SAVEAREA0: -4590,-655,24652,18633; SAVECOUNT: 26; TIME: 13:28:28; UPDATEDATE: 2017/01/31; UPDATETIME: 10:27:25; UPDATEUSER: s.maruyama; VAL1: 3A; VAL2: 200V; VAL3: A2-1PA-2.54DSA
D49 = ZD: ADSMODELNAME: s_CRZ15; CDMASTERCADCELG: MMK0167; COMP: PRT_6; COMPONENTTYPE: 4; FNLEADFREETHET1GT2GMCTH1: N_N_N; FORWARDVOLTAGEM: 0; GCOUNT: 1; MAXAVERAGEFORWA: 0; MAXGCOUNT: 1; MAXREPETITIVEPE: 0; MAXREVERSEVOLTA: 0; MOUNTINGFORMSMD: SMD; NOTMOUNT: NOT MOUNT; OUMECLASSIFICATION: èd³_CI[h; OUMEMAKER: TSB “ŒŽÅ; OUMEMAKERKATAMEI: CRZ15; OUMEPARTTYPE: D; PEAKFORWARDVOLT: 0; REVERSECURRENT: 0; USERCOMPTEXT3: TOSHIBA; VAL1: CRZ15; VAL3: CRZ15; ZENERVOLTAGEMAX: 16.5; ZENERVOLTAGEMIN: 13.5
IC3 = L28070: COMP: PRT_59; COMPONENTTYPE: 4; MAKER: TEXAS; VAL3: UCC28070A
IC11 = L70433: COMP: PRT_10; COMPONENTTYPE: 4; MAKER: TEXAS; VAL3: TLV70433DBVT
R1 R91 R92 R94 R95 = R: ADSMODELNAME: s_RK73H1JTTD1004F; CDMASTERCADCELG: KC0167; CHIPSIZE: 1608; COMP: PRT_8; COMPONENTTYPE: 4; FNLEADFREETHET1GT2GMCTH1: N_N_N; GCOUNT: 1; MAKER: KOA; MAXGCOUNT: 1; MOUNTINGFORMSMD: SMD; NOMINALRESISTAN: 1M; OUMECLASSIFICATION: \ÊÀpÅèïRí; OUMEMAKER: KOA R[A; OUMEMAKERKATAMEI: RK73H1JTTD1004F; POWERRATING: 100m; QUADMODEL: RES_1M; RESISTANCETOLER: F; SIZECODESMD: 1608; VAL1: 1M; VAL2: 100mW,}5%; VAL3: RK73B1JTTD105J
R2 = R: ADSMODELNAME: s_ERJ3GEYJ243V; CDMASTERCADCELG: KC0008; CHIPSIZE: 1608; COMP: PRT_8; COMPONENTTYPE: 4; FNLEADFREETHET1GT2GMCTH1: 3_1_N; GCOUNT: 1; MAKER: PANASONIC; MAXGCOUNT: 1; MOUNTINGFORMSMD: SMD; NOMINALRESISTAN: 24K; OUMECLASSIFICATION: \ÊÀpÅèïRí; OUMEMAKER: NAE pi\jbNGNgjbNfoCX; OUMEMAKERKATAMEI: ERJ3GEYJ243V; POWERRATING: 63m; QUADMODEL: RES_24K; RESISTANCETOLER: J; SIZECODESMD: 1608; VAL1: 23.2K; VAL2: 100mW,}1%; VAL3: ERJ-3EKF2322V
R89 = R: ADSMODELNAME: s_RK73H1JTTD1004F; CDMASTERCADCELG: KC0167; CHIPSIZE: 1608; COMP: PRT_8; COMPONENTTYPE: 4; FNLEADFREETHET1GT2GMCTH1: N_N_N; GCOUNT: 1; MAKER: KOA; MAXGCOUNT: 1; MOUNTINGFORMSMD: SMD; NOMINALRESISTAN: 1M; OUMECLASSIFICATION: \ÊÀpÅèïRí; OUMEMAKER: KOA R[A; OUMEMAKERKATAMEI: RK73H1JTTD1004F; POWERRATING: 100m; QUADMODEL: RES_1M; RESISTANCETOLER: F; SIZECODESMD: 1608; VAL1: 1M; VAL2: 100mW; VAL3: RK73B1JTTD105J
R90 = R: ADSMODELNAME: s_ERJ3EKF2202V; CDMASTERCADCELG: KC0008; CHIPSIZE: 1608; COMP: PRT_8; COMPONENTTYPE: 4; FNLEADFREETHET1GT2GMCTH1: N_N_N; GCOUNT: 1; MAKER: PANASONIC; MAXGCOUNT: 1; MOUNTINGFORMSMD: SMD; NOMINALRESISTAN: 22K; OUMECLASSIFICATION: \ÊÀpÅèïRí; OUMEMAKER: NAE pi\jbNGNgjbNfoCX; OUMEMAKERKATAMEI: ERJ3EKF2202V; POWERRATING: 100m; QUADMODEL: RES_22K; RESISTANCETOLER: F; SIZECODESMD: 1608; VAL1: 23.2K; VAL2: 100mW,}1%; VAL3: ERJ-3EKF2322V
R93 = R: ADSMODELNAME: s_ERJ3EKF1103V; CDMASTERCADCELG: KC0008; CHIPSIZE: 1608; COMP: PRT_8; COMPONENTTYPE: 4; FNLEADFREETHET1GT2GMCTH1: N_N_N; GCOUNT: 1; MAKER: PANASONIC; MAXGCOUNT: 1; MOUNTINGFORMSMD: SMD; NOMINALRESISTAN: 110K; OUMECLASSIFICATION: \ÊÀpÅèïRí; OUMEMAKER: NAE pi\jbNGNgjbNfoCX; OUMEMAKERKATAMEI: ERJ3EKF1103V; POWERRATING: 100m; QUADMODEL: RES_110K; RESISTANCETOLER: F; SIZECODESMD: 1608; VAL1: 115K; VAL2: 100mW,}1%; VAL3: ERJ-3EKF1153V
R96 = R: CHIPSIZE: 1608; COMP: PRT_8; COMPONENTTYPE: 4; MAKER: KOA; VAL1: 3.9k; VAL2: 100mW,}5%; VAL3: RK73B1JTTD392J
R97 = R: CHIPSIZE: 1608; COMP: PRT_8; COMPONENTTYPE: 4; MAKER: PANASONIC; VAL1: 3.65k; VAL2: 100mW,}1%; VAL3: ERJ-3EKF3651V
R98 R99 = R: ADSMODELNAME: s_RN73H1JTTD6801B10; CDMASTERCADCELG: KCK0203; CHIPSIZE: 1608; COMP: PRT_8; COMPONENTTYPE: 4; FNLEADFREETHET1GT2GMCTH1: N_N_N; GCOUNT: 1; MAKER: KOA; MAXGCOUNT: 1; MOUNTINGFORMSMD: SMD; NOMINALRESISTAN: 6.8K; OUMECLASSIFICATION: \ÊÀpÅèïRí; OUMEMAKER: KOA R[A; OUMEMAKERKATAMEI: RN73H1JTTD6801B10; PMPRODUCTSTYPEG: DME; POWERRATING: 100m; QUADMODEL: RES_6.8K; RESISTANCETOLER: B; SIZECODESMD: 1608; VAL1: 6.8K; VAL2: 100mW,}5%; VAL3: RK73B1JTTD682J
R100 = R: ADSMODELNAME: s_ERJ3EKF1203V; CDMASTERCADCELG: KC0008; CHIPSIZE: 1608; COMP: PRT_8; COMPONENTTYPE: 4; FNLEADFREETHET1GT2GMCTH1: N_N_N; GCOUNT: 1; MAKER: PANASONIC; MAXGCOUNT: 1; MOUNTINGFORMSMD: SMD; NOMINALRESISTAN: 120K; OUMECLASSIFICATION: \ÊÀpÅèïRí; OUMEMAKER: NAE pi\jbNGNgjbNfoCX; OUMEMAKERKATAMEI: ERJ3EKF1203V; POWERRATING: 100m; QUADMODEL: RES_120K; RESISTANCETOLER: F; SIZECODESMD: 1608; VAL1: 124K; VAL2: 100mW,}1%; VAL3: ERJ-3EKF1243V
R101 = R: CHIPSIZE: 1608; COMP: PRT_8; COMPONENTTYPE: 4; MAKER: PANASONIC; VAL1: 187k; VAL2: 100mW,}1%; VAL3: ERJ-3EKF1873V
R102 = R: ADSMODELNAME: s_RN73H1JTTD3002B10; CDMASTERCADCELG: KC0008; CHIPSIZE: 1608; COMP: PRT_8; COMPONENTTYPE: 4; FNLEADFREETHET1GT2GMCTH1: N_N_N; GCOUNT: 1; MAKER: KOA; MAXGCOUNT: 1; MOUNTINGFORMSMD: SMD; NOMINALRESISTAN: 30K; OUMECLASSIFICATION: \ÊÀpÅèïRí; OUMEMAKER: KOA R[A; OUMEMAKERKATAMEI: RN73H1JTTD3002B10; POWERRATING: 100m; QUADMODEL: RES_30K; RESISTANCETOLER: B; SIZECODESMD: 1608; VAL1: 30K; VAL2: 100mW,}1%; VAL3: RK73H1JTTD3002F
R103 = R: CHIPSIZE: 1608; COMP: PRT_8; COMPONENTTYPE: 4; MAKER: PANASONIC; VAL1: 115k; VAL2: 100mW,}1%; VAL3: ERJ-3EKF1153V
R104 = R: ADSMODELNAME: s_RK73B1JTTD104G; CDMASTERCADCELG: KC0008; CHIPSIZE: 1608; COMP: PRT_8; COMPONENTTYPE: 4; FNLEADFREETHET1GT2GMCTH1: N_N_N; GCOUNT: 1; MAKER: KOA; MAXGCOUNT: 1; MOUNTINGFORMSMD: SMD; NOMINALRESISTAN: 100K; OUMECLASSIFICATION: \ÊÀpÅèïRí; OUMEMAKER: KOA R[A; OUMEMAKERKATAMEI: RK73B1JTTD104G; POWERRATING: 100m; QUADMODEL: RES_100K; RESISTANCETOLER: G; SIZECODESMD: 1608; VAL1: 100K; VAL2: 100mW,}5%; VAL3: RK73B1JTTD104J
R117 = R: ADSCNVFLAG: ON; ADSCOMPONENTNAME: R_1005; ADSMODELNAME: s_ERJ2GE0R00X; CDMASTERCADCELG: KC0005; CHIPSIZE: 1608; COMP: PRT_8; COMPONENTTYPE: 4; FNLEADFREETHET1GT2GMCTH1: 2_1_N; GCOUNT: 1; ICX_PART_MODEL: RES_0; MAKER: KOA; MAXGCOUNT: 1; MOUNTINGFORMSMD: SMD; NOMINALRESISTAN: 0; OUMECLASSIFICATION: \ÊÀpÅèïRí; OUMEMAKER: NAE pi\jbNGNgjbNfoCX; OUMEMAKERKATAMEI: ERJ2GE0R00X; PMPRODUCTSTYPEG: HD1-PC1; POWERRATING: 63m; QUADMODEL: RES_0; RESISTANCETOLER: X; SIZECODESMD: 1005; SQ_PART_MODEL: RES_0; VAL1: 0; VAL2: 100mW; VAL3: RK73Z1JTTD
R130 = R: ADSMODELNAME: s_ERJPA3F1000V@@; CDMASTERCADCELG: KC0165; CHIPSIZE: 1608; COMP: PRT_8; COMPONENTTYPE: 4; FNLEADFREETHET1GT2GMCTH1: N_N_N; GCOUNT: 1; MAKER: KOA; MAXGCOUNT: 1; MOUNTINGFORMSMD: SMD; NOMINALRESISTAN: 100; OUMECLASSIFICATION: \ÊÀpÅèïRí; OUMEMAKER: NAE pi\jbNGNgjbNfoCX; OUMEMAKERKATAMEI: ERJPA3F1000V@@; PMPRODUCTSTYPEG: DA; POWERRATING: 250m; QUADMODEL: RES_100; RESISTANCETOLER: F; SIZECODESMD: 1608; VAL1: 100; VAL2: 125mW,}5%; VAL3: RK73B1JTTD101J
R169 = R: ADSMODELNAME: s_RK73B1JTTD102G; CDMASTERCADCELG: KCK0203; CHIPSIZE: 1608; COMP: PRT_8; COMPONENTTYPE: 4; FNLEADFREETHET1GT2GMCTH1: N_N_N; GCOUNT: 1; MAKER: KOA; MAXGCOUNT: 1; MOUNTINGFORMSMD: SMD; NOMINALRESISTAN: 1K; OUMECLASSIFICATION: \ÊÀpÅèïRí; OUMEMAKER: KOA R[A; OUMEMAKERKATAMEI: RK73B1JTTD102G; PMPRODUCTSTYPEG: DME; POWERRATING: 100m; QUADMODEL: RES_1K; RESISTANCETOLER: G; SIZECODESMD: 1608; VAL1: 1K; VAL2: 125mW,}5%; VAL3: RK73B1JTTD102J
R170 = R: ADSMODELNAME: s_RK73B1JTTD102G; CDMASTERCADCELG: KCK0203; CHIPSIZE: 1608; COMP: PRT_8; COMPONENTTYPE: 4; FNLEADFREETHET1GT2GMCTH1: N_N_N; GCOUNT: 1; MAKER: KOA; MAXGCOUNT: 1; MOUNTINGFORMSMD: SMD; NOMINALRESISTAN: 1K; OLDCOMPONENTID: 100; OUMECLASSIFICATION: \ÊÀpÅèïRí; OUMEMAKER: KOA R[A; OUMEMAKERKATAMEI: RK73B1JTTD102G; PMPRODUCTSTYPEG: DME; POWERRATING: 100m; QUADMODEL: RES_1K; RESISTANCETOLER: G; SIZECODESMD: 1608; VAL1: 1K; VAL2: 125mW,}5%; VAL3: RK73B1JTTD102J
R171 = R: ADSMODELNAME: s_RK73Z1JTTD; CDMASTERCADCELG: KCK0203; CHIPSIZE: 1608; COMP: PRT_8; COMPONENTTYPE: 4; FNLEADFREETHET1GT2GMCTH1: 3_2_N; GCOUNT: 1; MAKER: KOA; MAXGCOUNT: 1; MOUNTINGFORMSMD: SMD; NOMINALRESISTAN: 0; NOTMOUNT: NOT MOUNT; OUMECLASSIFICATION: \ÊÀpÅèïRí; OUMEMAKER: KOA R[A; OUMEMAKERKATAMEI: RK73Z1JTTD; PMPRODUCTSTYPEG: DME-HD1-PC1; POWERRATING: 100m; QUADMODEL: RES_0; RESISTANCETOLER: X; SIZECODESMD: 1608; VAL1: 0; VAL2: 100mW; VAL3: RK73Z1JTTD
R174-R177 R198 = R: CHIPSIZE: 1608; COMP: PRT_8; COMPONENTTYPE: 4; MAKER: KOA; NOTMOUNT: NOT MOUNT; VAL1: 0; VAL2: 100mW; VAL3: RK73Z1JTTD
R227 R228 = R: CHIPSIZE: 1608; COMP: PRT_8; COMPONENTTYPE: 4; MAKER: KOA; VAL1: 680; VAL2: 100mW,}1%; VAL3: RK73H1JTTD6800F
TP43 = TP: COMP: PRT_49; COMPONENTKIND: 111; COMPONENTTYPE: 4; MAKER: MAC8; VAL3: LC-22-S-WHITE
U?#5 = WAKU_DEF100: COMPONENTTYPE: 2; DATE: 2017-12-25; DESIGNED: TOSHIBA; DRAWINGNUMBER: RD001-SCHEMATIC02; FUNCTION: PFC - Controller; PAGENUMBER: 3; REVISION: 02; SAVEAREA0: -45080,-4508,463680,304612; SHEETNUMBER: 3/8; TIME: 14:20:16; TITLE: 1.6kW Server Power Supply; UPDATEDATE: 2017/12/25; UPDATETIME: 13:49:58; UPDATEUSER: f1043010
C18 = C: ADSCNVFLAG: ON; ADSCOMPONENTNAME: C_1005; ADSMODELNAME: s_C1005JB1C224KT; CAPACITANCETOLE: K; CDMASTERCADCELG: KC0005; CHIPSIZE: 1005; COMP: PRT_52; COMPONENTTYPE: 4; FNLEADFREETHET1GT2GMCTH1: N_N_N; GCOUNT: 1; ICX_PART_MODEL: CON_220N; MAKER: TDK; MAXGCOUNT: 1; NOMINALCAPACITA: 220n; OUMECLASSIFICATION: ƒZƒ‰ƒ~ƒbƒNƒRƒ“ƒfƒ“ƒT; OUMEMAKER: TDK ‚s‚c‚j; OUMEMAKERKATAMEI: C1005JB1C224KT; QUADMODEL: CON_220N; RATEDVOLTAGE: 16; SIZECODESMD: 1005; SQ_PART_MODEL: CON_220N; TEMPCHARACTERI2: B; VAL1: 100nF; VAL2: 25V,}10%; VAL3: C1005X7R1E104K050BB
C19 = C: ADSMODELNAME: s_C1005JB1C224KT; CAPACITANCETOLE: K; CDMASTERCADCELG: KC0005; CHIPSIZE: 1005; COMP: PRT_52; COMPONENTTYPE: 4; FNLEADFREETHET1GT2GMCTH1: N_N_N; GCOUNT: 1; MAKER: TDK; MAXGCOUNT: 1; NOMINALCAPACITA: 220n; OUMECLASSIFICATION: ƒZƒ‰ƒ~ƒbƒNƒRƒ“ƒfƒ“ƒT; OUMEMAKER: TDK ‚s‚c‚j; OUMEMAKERKATAMEI: C1005JB1C224KT; QUADMODEL: CON_220N; RATEDVOLTAGE: 16; SIZECODESMD: 1005; TEMPCHARACTERI2: B; VAL1: 100nF; VAL2: 25V,}10%; VAL3: C1005X7R1E104K050BB
C53 C54 C56 C57 = C: ADSMODELNAME: s_GCM1885C1H221JA16D; CAPACITANCETOLE: J; CDMASTERCADCELG: KC0008; CHIPSIZE: 1608; COMP: PRT_48; COMPONENTTYPE: 4; FNLEADFREETHET1GT2GMCTH1: N_N_N; GCOUNT: 1; MAKER: MURATA; MAXGCOUNT: 1; NOMINALCAPACITA: 220p; NOTMOUNT: NOT MOUNT; OUMECLASSIFICATION: ƒZƒ‰ƒ~ƒbƒNƒRƒ“ƒfƒ“ƒT; OUMEMAKER: MRT ºc»ì; OUMEMAKERKATAMEI: GCM1885C1H221JA16D; PMPRODUCTSTYPEG: DME; QUADMODEL: CON_220P; RATEDVOLTAGE: 50; SIZECODESMD: 1608; VAL1: 220pF; VAL2: 50V,}5%; VAL3: GRM1885C1H221JA01D
C55 = C: ADSCNVFLAG: ON; ADSCOMPONENTNAME: C_1005; ADSMODELNAME: s_GRM155R61A225KE95D; CAPACITANCETOLE: K; CDMASTERCADCELG: KC0005; CHIPSIZE: 1005; COMP: PRT_52; COMPONENTTYPE: 4; FNLEADFREETHET1GT2GMCTH1: N_N_N; GCOUNT: 1; ICX_PART_MODEL: CON_2.2U; MAKER: TDK; MAXGCOUNT: 1; NOMINALCAPACITA: 2.2u; OUMECLASSIFICATION: ƒZƒ‰ƒ~ƒbƒNƒRƒ“ƒfƒ“ƒT; OUMEMAKER: MRT ºc»ì; OUMEMAKERKATAMEI: GRM155R61A225KE95D; PMPRODUCTSTYPEG: HD1; QUADMODEL: CON_2.2U; RATEDVOLTAGE: 10; SIZECODESMD: 1005; SQ_PART_MODEL: CON_2.2U; VAL1: 1uF; VAL2: 25V,}20%; VAL3: C1005X5R1E105M050BC
C58 = C: ADSMODELNAME: s_GRM155R61A225KE95D; CAPACITANCETOLE: K; CDMASTERCADCELG: KC0005; CHIPSIZE: 1005; COMP: PRT_52; COMPONENTTYPE: 4; FNLEADFREETHET1GT2GMCTH1: N_N_N; GCOUNT: 1; MAKER: TDK; MAXGCOUNT: 1; NOMINALCAPACITA: 2.2u; OUMECLASSIFICATION: ƒZƒ‰ƒ~ƒbƒNƒRƒ“ƒfƒ“ƒT; OUMEMAKER: MRT ºc»ì; OUMEMAKERKATAMEI: GRM155R61A225KE95D; PMPRODUCTSTYPEG: HD1; QUADMODEL: CON_2.2U; RATEDVOLTAGE: 10; SIZECODESMD: 1005; VAL1: 1uF; VAL2: 25V,}20%; VAL3: C1005X5R1E105M050BC
D16 D17 = D: ADSMODELNAME: s_MURS220T3G; CDMASTERCADCELG: DD924D; COMP: PRT_14; COMPONENTTYPE: 4; FNLEADFREETHET1GT2GMCTH1: 3_0_N; FORWARDVOLTAGEM: 0; GCOUNT: 1; MAKER: TOSHIBA; MAXAVERAGEFORWA: 2; MAXGCOUNT: 1; MAXREPETITIVEPE: 200; MAXREVERSEVOLTA: 0; MOUNTINGFORMSMD: SMD; OUMECLASSIFICATION: êÊ®¬fq; OUMEMAKER: ONS IZ~R_N^[; OUMEMAKERKATAMEI: MURS220T3G; PEAKFORWARDVOLT: 770m; PMPRODUCTSTYPEG: PJ1; REVERSECURRENT: 50u; USERCOMPTEXT3: TOSHIBA; VAL3: CMF01; ZENERVOLTAGEMAX: 0; ZENERVOLTAGEMIN: 0
D18 D19 = D: ADSMODELNAME: s_MURS340T3G@@; CDMASTERCADCELG: KD0125; COMP: PRT_14; COMPONENTTYPE: 4; FNLEADFREETHET1GT2GMCTH1: N_N_N; FORWARDVOLTAGEM: 0; GCOUNT: 1; MAKER: TOSHIBA; MAXAVERAGEFORWA: 4; MAXGCOUNT: 1; MAXREPETITIVEPE: 400; MAXREVERSEVOLTA: 0; MOUNTINGFORMSMD: SMD; OUMECLASSIFICATION: êÊ®¬fq; OUMEMAKER: ONS IZ~R_N^[; OUMEMAKERKATAMEI: MURS340T3G@@; PEAKFORWARDVOLT: 1.28; PMPRODUCTSTYPEG: HEV; REVERSECURRENT: 250u; USERCOMPTEXT3: TOSHIBA; VAL3: CMF01; ZENERVOLTAGEMAX: 0; ZENERVOLTAGEMIN: 0
D22-D25 = DMH: COMP: PRT_25; COMPONENTTYPE: 4; MAKER: TOSHIBA; USERCOMPTEXT3: TOSHIBA; VAL3: TBAT54
D40-D47 = SBD: COMP: PRT_11; COMPONENTTYPE: 4; MAKER: TOSHIBA; USERCOMPTEXT3: TOSHIBA; VAL1: CUS01(TE85L,Q); VAL3: CUS01(TE85L,Q)
IC4 IC5 = L27714: COMP: PRT_58; COMPONENTTYPE: 4; MAKER: TEXAS; VAL3: UCC27714DR
L3 = JP: ADSMODELNAME: s_ERJ3GEY0R00V; CDMASTERCADCELG: KC0008; COMP: PRT_64; COMPONENTTYPE: 4; FNLEADFREETHET1GT2GMCTH1: 2_1_N; GCOUNT: 1; MAXGCOUNT: 1; MOUNTINGFORMSMD: SMD; NOMINALRESISTAN: 0; OUMECLASSIFICATION: \ÊÀpÅèïRí; OUMEMAKER: NAE pi\jbNGNgjbNfoCX; OUMEMAKERKATAMEI: ERJ3GEY0R00V; OUMEPARTTYPE: R; PMPRODUCTSTYPEG: HD1-PC1; POWERRATING: 100m; QUADMODEL: RES_0; RESISTANCETOLER: X; SIZECODESMD: 1608; VAL1: 0(X); VAL2: 100mW; VAL3: 22AWGÅÅZÅp^[V[g
Q3-Q6 = MFNF: COMP: PRT_9; COMPONENTTYPE: 4; MAKER: TOSHIBA; USERCOMPTEXT3: TOSHIBA; VAL3: TK25N60X5
R9 = R: ADSCNVFLAG: ON; ADSCOMPONENTNAME: R_3216; ADSMODELNAME: s_RK73H2BTTD4871F; CDMASTERCADCELG: DR901A; CHIPSIZE: 1608; COMP: PRT_8; COMPONENTTYPE: 4; FNLEADFREETHET1GT2GMCTH1: 3_1_N; GCOUNT: 1; ICX_PART_MODEL: RES_4.87K; MAKER: KOA; MAXGCOUNT: 1; MOUNTINGFORMSMD: SMD; NOMINALRESISTAN: 4.87K; OUMECLASSIFICATION: \ÊÀpÅèïRí; OUMEMAKER: KOA R[A; OUMEMAKERKATAMEI: RK73H2BTTD4871F; POWERRATING: 250m; QUADMODEL: RES_4.87K; RESISTANCETOLER: F; SIZECODESMD: 3216; SQ_PART_MODEL: RES_4.87K; VAL1: 2k; VAL2: 100mW,}5%; VAL3: RK73B1JTTD202J
R110-R113 = R: ADSMODELNAME: s_RK73Z1JTTD; CDMASTERCADCELG: KCK0203; CHIPSIZE: 1608; COMP: PRT_8; COMPONENTTYPE: 4; FNLEADFREETHET1GT2GMCTH1: 3_2_N; GCOUNT: 1; MAKER: KOA; MAXGCOUNT: 1; MOUNTINGFORMSMD: SMD; NOMINALRESISTAN: 0; OUMECLASSIFICATION: \ÊÀpÅèïRí; OUMEMAKER: KOA R[A; OUMEMAKERKATAMEI: RK73Z1JTTD; PMPRODUCTSTYPEG: DME-HD1-PC1; POWERRATING: 100m; QUADMODEL: RES_0; RESISTANCETOLER: X; SIZECODESMD: 1608; VAL1: 0; VAL2: 100mW; VAL3: RK73Z1JTTD
R114 = R: ADSMODELNAME: s_RK73B2ETTD2R2J; CDMASTERCADCELG: DR903A; CHIPSIZE: 3225; COMP: PRT_23; COMPONENTTYPE: 4; FNLEADFREETHET1GT2GMCTH1: N_N_N; GCOUNT: 1; MAKER: PANASONIC; MAXGCOUNT: 1; MOUNTINGFORMSMD: SMD; NOMINALRESISTAN: 2.2; OUMECLASSIFICATION: \ÊÀpÅèïRí; OUMEMAKER: KOA R[A; OUMEMAKERKATAMEI: RK73B2ETTD2R2J; POWERRATING: 500m; QUADMODEL: RES_2.2; RESISTANCETOLER: J; SIZECODESMD: 3225; VAL1: 2.2; VAL2: 500mW,}5%; VAL3: ERJ-14YJ2R2U
R115 = R: ADSMODELNAME: s_SG73P2ETTD2R2J; CDMASTERCADCELG: KC0013; CHIPSIZE: 3225; COMP: PRT_23; COMPONENTTYPE: 4; FNLEADFREETHET1GT2GMCTH1: 3_0_N; GCOUNT: 1; MAKER: PANASONIC; MAXGCOUNT: 1; MOUNTINGFORMSMD: SMD; NOMINALRESISTAN: 2.2; OUMECLASSIFICATION: \ÊÀpÅèïRí; OUMEMAKER: KOA R[A; OUMEMAKERKATAMEI: SG73P2ETTD2R2J; PMPRODUCTSTYPEG: SV1; POWERRATING: 500m; QUADMODEL: RES_2.2; RESISTANCETOLER: J; SIZECODESMD: 3225; VAL1: 2.2; VAL2: 500mW,}5%; VAL3: ERJ-14YJ2R2U
R122 R123 = R: ADSMODELNAME: s_ERJ3RQJ1R0V@@; CDMASTERCADCELG: KC0165; CHIPSIZE: 1608; COMP: PRT_8; COMPONENTTYPE: 4; FNLEADFREETHET1GT2GMCTH1: N_N_N; GCOUNT: 1; MAKER: PANASONIC; MAXGCOUNT: 1; MOUNTINGFORMSMD: SMD; NOMINALRESISTAN: 1; OUMECLASSIFICATION: \ÊÀpÅèïRí; OUMEMAKER: NAE pi\jbNGNgjbNfoCX; OUMEMAKERKATAMEI: ERJ3RQJ1R0V@@; PMPRODUCTSTYPEG: DA; POWERRATING: 100m; QUADMODEL: RES_1; RESISTANCETOLER: J; SIZECODESMD: 1608; VAL1: 1; VAL2: 100mW,}5%; VAL3: ERJ-3GEYJ1R0V
R126 R127 R132-R137 = R: ADSMODELNAME: s_RL1632H_R001_JN; CDMASTERCADCELG: KC0020; CHIPSIZE: 3216; COMP: PRT_5; COMPONENTTYPE: 4; FNLEADFREETHET1GT2GMCTH1: N_N_N; GCOUNT: 1; MAKER: KOA; MAXGCOUNT: 1; MOUNTINGFORMSMD: SMD; NOMINALRESISTAN: 1m; OUMECLASSIFICATION: \ÊÀpÅèïRí; OUMEMAKER: SSM iHÆ; OUMEMAKERKATAMEI: RL1632H-R001-JN; POWERRATING: 500m; QUADMODEL: RES_1M; RESISTANCETOLER: J; SIZECODESMD: 3216; VAL1: 0; VAL2: 500mW; VAL3: RK73Z2BTTD
R178 R179 = R: CHIPSIZE: 6432; COMP: PRT_43; COMPONENTTYPE: 4; MAKER: VISHAY; VAL1: 300K; VAL2: 1W,}5%; VAL3: CRCW2512300KJNEG
T4 = T2AA: COMP: PRT_65; COMPONENTTYPE: 4; GCOUNT: 1; INDUCTANCEMAX: 0; INDUCTANCEMIN: 0; MAKER: PULSE; MAXGCOUNT: 1; MOUNTINGFORMSMD: DIP; NOMINALINDUCTA1: 140u; NOMINALINDUCTA2: X; VAL1: 1:100; VAL3: PE-63587
U?#4 = WAKU_DEF100: COMPONENTTYPE: 2; DATE: 2017-12-25; DESIGNED: TOSHIBA; DRAWINGNUMBER: RD001-SCHEMATIC02; FUNCTION: PSFB - Primary Bridge; PAGENUMBER: 4; REVISION: 02; SAVEAREA0: -45080,-4508,463680,304612; SHEETNUMBER: 4/8; TIME: 15:47:55; TITLE: 1.6kW Server Power Supply; UPDATEDATE: 2017/12/25; UPDATETIME: 13:49:58; UPDATEUSER: f1043010

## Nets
VCC3R3_1: R117.2 ; also on sheet 2
VCC12R0_1: IC2.1 IC2.8 R83.2 R87.2 R116.2 R120.1 R121.1 R122.1 R123.1 R130.1 ; also on sheet 8
$BN000001: R90.2 R227.1
$BN000002: R2.2 R228.1
CONN002: C19.1 D24.A IC4.11 Q3.S Q4.D R31.1 ; also on sheet 4
CONN003: D18.C D19.A L3.2 ; also on sheet 4
CS: D14.C ; also on sheet 3
CSA: D13.C D33.C R7.2 R87.1 R170.1 TP2.1
CSB: D12.C D31.C R8.2 R83.1 R169.1 TP1.1
GDA: C81.2 IC2.2 IC3.14 TP5.1
GDB: C80.2 IC2.4 IC3.17 TP6.1
Input12V_1: CN2.1 R116.1
LGND: R9.1 T4.3 ; also on sheet 1 2 3 4
OUTA1: R111.1 ; also on sheet 2
OUTB1: R110.1 ; also on sheet 2
OUTC1: R113.1 ; also on sheet 2
OUTD1: R112.1 ; also on sheet 2
PFC_OUT: C1.2 C7.2 D1.C D2.C D3.1 R92.2 R178.2 T4.2 TP44.1
PFC_VIN: D8.C D9.C R95.2
PN: C1.1 C7.1 C34.1 C35.1 C36.1 C37.1 C38.1 C39.1 C40.1 C42.1 C43.1 C45.1 C47.1 C48.1 C49.1 C50.1 C53.1 C54.1 C55.1 C56.1 C57.1 C58.1 C62.1 C66.1 C67.1 C75.1 C76.1 C77.1 C80.1 C81.1 C82.1 C83.1 C84.1 C85.1 C86.1 C87.1 CN3.1 D3.4 D18.A D22.A D25.A D49.A IC2.3 IC3.16 IC4.3 IC4.5 IC5.3 IC5.5 IC11.1 Q1.S Q2.S Q4.S Q6.S R2.1 R7.1 R8.1 R29.1 R33.1 R71.1 R73.1 R90.1 R93.1 R96.1 R98.1 R99.1 R100.1 R101.1 R102.1 R103.1 R104.1 R174.1 R175.1 R176.1 R179.1 R198.1 T2.2 T3.2 TP43.1 ; also on sheet 2 8
SIG6: D3.3 D9.A L2.1 ; also on sheet 8
SIG8: D3.2 D8.A L1.1 ; also on sheet 8
SIG11: D2.A L2.2 T2.4
SIG12: D1.A L1.2 T3.4
SIG15: D12.A R81.2 T2.1
SIG16: C34.2 R81.1
SIG18: Q2.D T2.3
SIG20: D13.A R85.2 T3.1
SIG21: C36.2 R85.1
SIG22: Q1.D T3.3
SIG23: FB1.1 R71.2 R72.2 R108.2
SIG24: C35.2 D31.A R82.2 R172.2
SIG25: C37.2 D33.A R86.2 R173.2
SIG27: FB2.1 R73.2 R74.2 R109.2
SIG30: D32.C D38.A D39.C IC2.7 R86.1
SIG39: R89.2 R91.1
SIG40: R91.2 R92.1
SIG43: C45.2 C46.2 IC3.11
SIG44: C46.1 R99.2
SIG45: C43.2 C44.2 IC3.12
SIG46: C44.1 R98.2
SIG47: C40.2 C41.2 IC3.3
SIG48: C41.1 R93.2
SIG49: C39.2 IC3.4 R89.1 R227.2 TP8.1
SIG50: C49.2 IC3.18
SIG51: C50.2 IC3.1 R171.1
SIG52: IC3.19 R100.2 R198.2
SIG53: IC3.7 R101.2 R176.2
SIG54: IC3.6 R102.2 R175.2
SIG55: IC3.20 R103.2 R174.2
SIG56: IC3.2 R104.2
SIG60: R94.2 R95.1
SIG61: R1.2 R94.1
SIG62: C38.2 IC3.5 R1.1 R228.2 TP7.1
SIG65: C19.2 D17.C IC4.13
SIG75: C18.2 D16.C IC5.13
SIG82: Q6.G R29.2 R136.2 R137.2 TP14.1
SIG86: C47.2 C48.2 D49.C IC3.15 R120.2
SIG89: C54.2 IC5.1 R111.2 TP38.1
SIG90: C53.2 IC5.2 R110.2 TP39.1
SIG91: C58.2 C84.2 C85.2 IC4.7 R115.1 R122.2
SIG92: D17.A R115.2
SIG93: C57.2 IC4.1 R113.2 TP9.1
SIG94: C56.2 IC4.2 R112.2 TP10.1
SIG95: D16.A R114.2
SIG100: D36.C R72.1
SIG101: D37.A R108.1
SIG102: D30.C D36.A D37.C IC2.5 R82.1
SIG104: C62.2 C82.2 C83.2 IC2.6 R121.2
SIG105: D39.A R109.1
SIG106: D38.C R74.1
SIG185: C67.2 IC11.3 R117.1
SIG205: Q4.G R33.2 R134.2 R135.2 TP12.1
SIG206: Q3.G R31.2 R126.2 R127.2 TP11.1
SIG223: C66.2 IC11.2 R130.2
SIG249: C18.1 D23.A IC5.11 L3.1 Q5.S Q6.D R28.1 TP15.1
SIGN254: D30.A R172.1
SIGN255: D32.A R173.1
SIGN256: C77.2 IC3.10 R96.2 R97.1 R177.1
SIGN260: C76.2 IC3.9 R170.2
SIGN262: C75.2 IC3.8 R169.2
SIGN266: FB1.2 Q2.G TP3.1
SIGN267: FB2.2 Q1.G TP4.1
SIGN269: D23.C D42.A D43.C IC5.12
SIGN270: C55.2 C86.2 C87.2 IC5.7 R114.1 R123.2
SIGN271: R178.1 R179.2
SIGN316: D40.C R126.1
SIGN317: D41.A R127.1
SIGN318: D24.C D40.A D41.C IC4.12
SIGN319: D42.C R132.1
SIGN320: D43.A R133.1
SIGN321: Q5.G R28.2 R132.2 R133.2 TP13.1
SIGN322: D22.C D46.A D47.C IC5.6
SIGN323: D46.C R136.1
SIGN324: D47.A R137.1
SIGN325: D25.C D44.A D45.C IC4.6
SIGN326: D45.A R135.1
SIGN327: D44.C R134.1
SIGN355: D19.C Q3.D Q5.D T4.1
SIGN356: D14.A R9.2 T4.5(4)
VREF_PFC: C42.2 IC3.13 R97.2 R171.2 R177.2

Not connected (* = marked no-connect by the designer): D22 NC; D23 NC; D24 NC; D25 NC; IC4 4 8 9 10 14; IC5 4 8 9 10 14; IC11 4 5; T4 4 6 7

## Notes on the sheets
sheet 5
- for current measurement
- for current measurement
- terminals have to be shorted with
  #22 AWG wire
  (minimal length)
sheet 6
- External 12V power supply for primary side
- for current
  measurement
sheet 7
- for current measurement
